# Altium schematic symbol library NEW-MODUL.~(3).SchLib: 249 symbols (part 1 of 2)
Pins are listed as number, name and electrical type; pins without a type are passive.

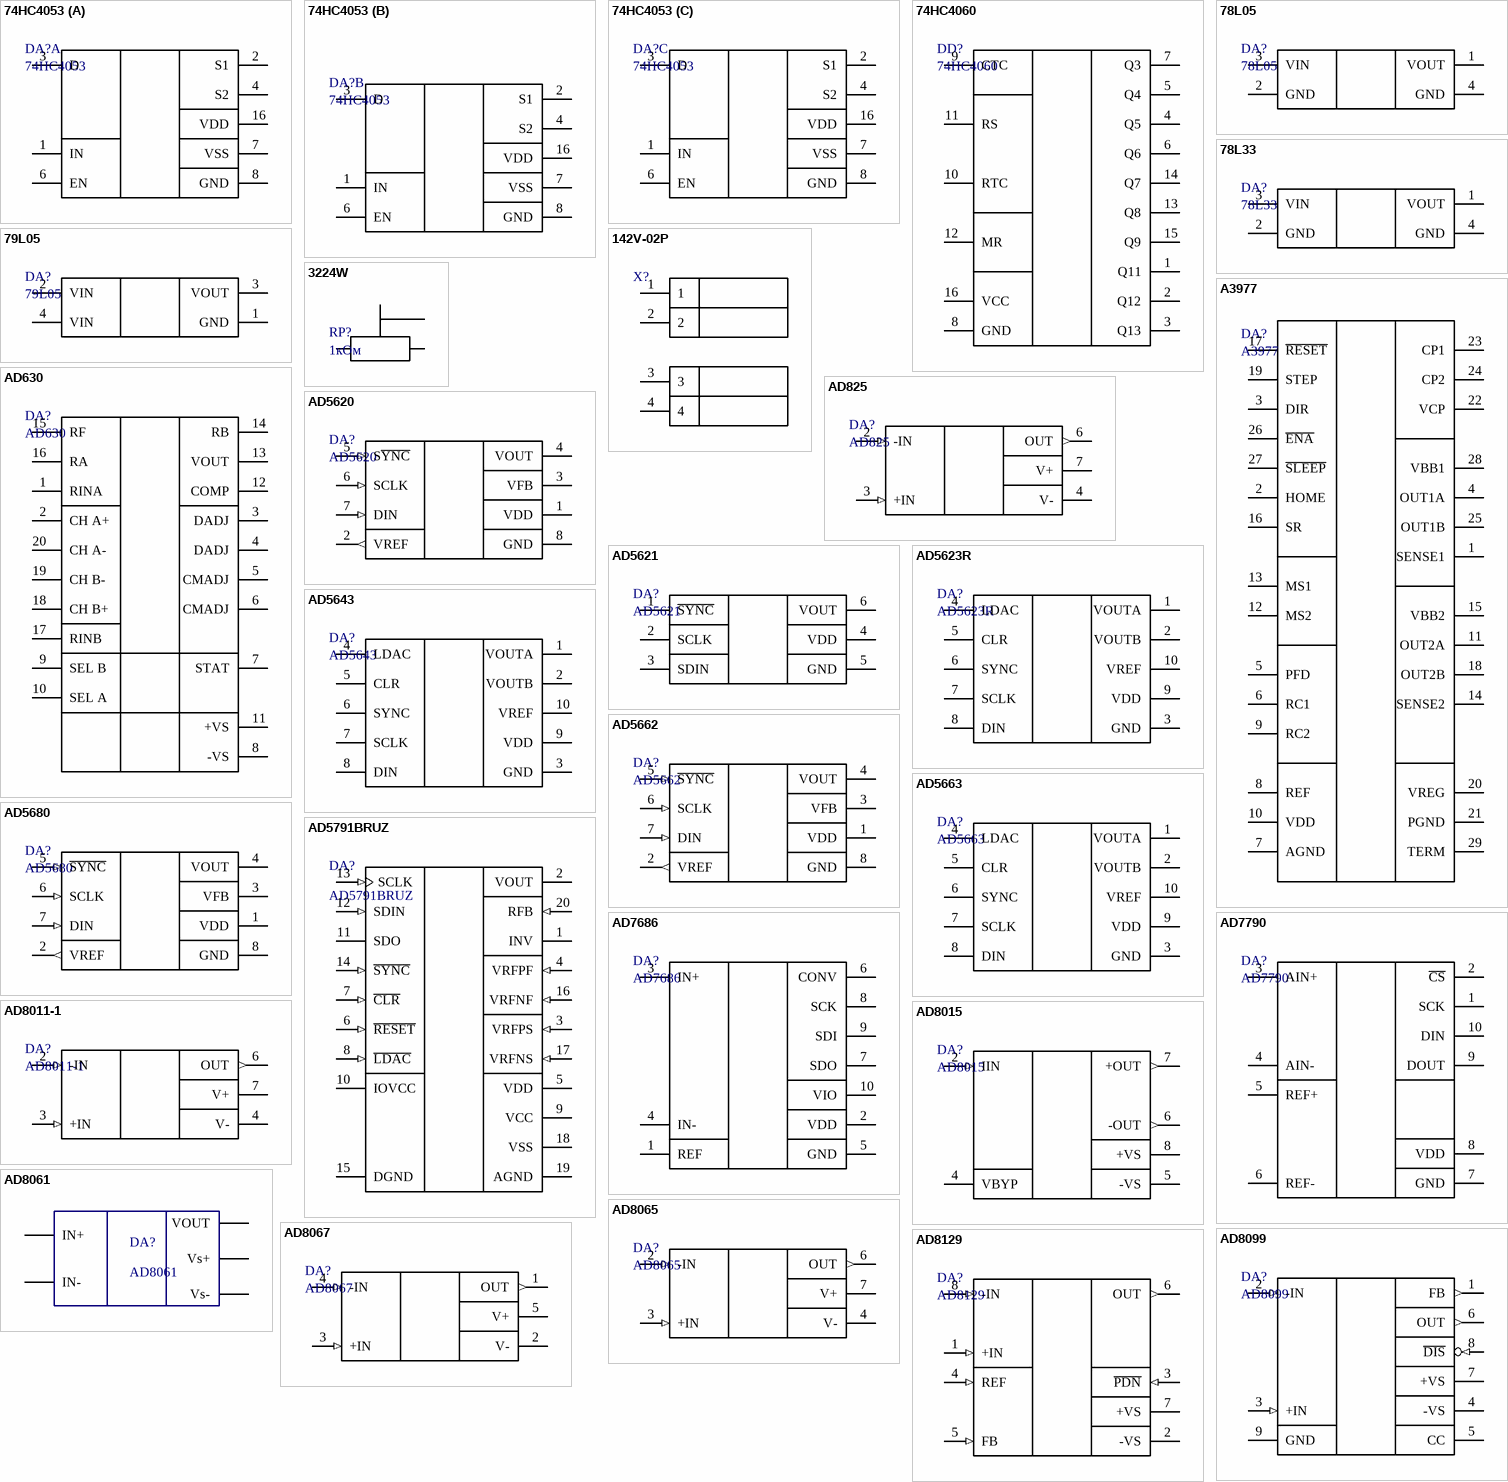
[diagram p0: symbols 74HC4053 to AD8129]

## 74HC4053
designator DA?
footprint R-16A_M (16-Pin Small Outline Integrated Circuit 1.27 mm Pitch, IPC Low Density)
part A pins: 1 IN, 2 S1, 3 D, 4 S2, 6 EN, 7 VSS, 8 GND, 16 VDD
part B pins: 1 IN, 2 S1, 3 D, 4 S2, 6 EN, 7 VSS, 8 GND, 16 VDD
part C pins: 1 IN, 2 S1, 3 D, 4 S2, 6 EN, 7 VSS, 8 GND, 16 VDD

## 74HC4060
designator DD?
14-stage binary ripple counter with oscillator
footprint R-16A_M (16-Pin Small Outline Integrated Circuit 1.27 mm Pitch, IPC Low Density)
pins: 1 Q11, 2 Q12, 3 Q13, 4 Q5, 5 Q4, 6 Q6, 7 Q3, 8 GND, 9 CTC, 10 RTC, 11 RS, 12 MR, 13 Q8, 14 Q7, 15 Q9, 16 VCC

## 78L05
designator DA?
footprint SOT89 (SOT-89; Body 4.6 x 4.25 mm, inc. leads (LxW max))
pins: 1 VOUT, 2 GND, 3 VIN, 4 GND

## 78L33
designator DA?
footprint SOT89 (SOT-89; Body 4.6 x 4.25 mm, inc. leads (LxW max))
pins: 1 VOUT, 2 GND, 3 VIN, 4 GND

## 79L05
designator DA?
footprint SOT89 (SOT-89; Body 4.6 x 4.25 mm, inc. leads (LxW max))
pins: 1 GND, 2 VIN, 3 VOUT, 4 VIN

## 142V-02P
designator X?  (value not drawn)
footprint 142V-02P
pins: 1, 2, 3, 4

## 3224W
designator RP?, comment 1кОм
подстроечный резистор
footprint 3224W
pins: 1, 2, 3

## A3977
designator DA?
footprint TSOP65P640-28AM - THERMAL-PAD (TSOP, 28-Leads, Body 9.7x4.4mm, Pitch 0.65mm, IPC Low Density)
pins: 1 SENSE1, 2 HOME, 3 DIR, 4 OUT1A, 5 PFD, 6 RC1, 7 AGND, 8 REF, 9 RC2, 10 VDD, 11 OUT2A, 12 MS2, 13 MS1, 14 SENSE2, 15 VBB2, 16 SR, 17 ~{RESET}, 18 OUT2B, 19 STEP, 20 VREG, 21 PGND, 22 VCP, 23 CP1, 24 CP2, 25 OUT1B, 26 ~{ENA}, 27 ~{SLEEP}, 28 VBB1, 29 TERM

## AD630
designator DA?
Balanced Modulator/Demodulator
footprint SOL-20_M (20-Pin Small Outline Integrated Circuit 1.27 mm Pitch, IPC Low Density)
pins: 1 RINA, 2 CH A+, 3 DADJ, 4 DADJ, 5 CMADJ, 6 CMADJ, 7 STAT, 8 -VS, 9 SEL B, 10 SEL A, 11 +VS, 12 COMP, 13 VOUT, 14 RB, 15 RF, 16 RA, 17 RINB, 18 CH B+, 19 CH B-, 20 CH A-

## AD825
designator DA?
FET OP
footprint SOIC127P600-8BM (SOIC, 8-Leads, Body 4.9x3.9mm, Pitch 1.27mm, IPC Low Density)
pins: 2 -IN (in), 3 +IN (in), 4 V- (power), 6 OUT (out), 7 V+ (power)

## AD5620
designator DA?
footprint UMAX8 (Shrink Small Outline; 8 Leads; Body Width 3 mm; Pitch 0.65 mm)
pins: 1 VDD (power), 2 VREF (out), 3 VFB, 4 VOUT, 5 S~{YNC} (in), 6 SCLK (in), 7 DIN (in), 8 GND

## AD5621
designator DA?
footprint ADI-KS-6_N (SOT23, 6-Leads, Body 2x1.25mm, Pitch 0.65mm, IPC Medium Density)
pins: 1 ~{SYNC}, 2 SCLK, 3 SDIN, 4 VDD, 5 GND, 6 VOUT

## AD5623R
designator DA?
footprint UMAX10 (Shrink Small Outline; 10 Leads; Body Width 3 mm; Pitch 0.5 mm)
pins: 1 VOUTA, 2 VOUTB, 3 GND, 4 LDAC, 5 CLR, 6 SYNC, 7 SCLK, 8 DIN, 9 VDD, 10 VREF

## AD5643
designator DA?
footprint UMAX10 (Shrink Small Outline; 10 Leads; Body Width 3 mm; Pitch 0.5 mm)
pins: 1 VOUTA, 2 VOUTB, 3 GND, 4 LDAC, 5 CLR, 6 SYNC, 7 SCLK, 8 DIN, 9 VDD, 10 VREF

## AD5662
designator DA?
footprint UMAX8 (Shrink Small Outline; 8 Leads; Body Width 3 mm; Pitch 0.65 mm)
pins: 1 VDD (power), 2 VREF (out), 3 VFB, 4 VOUT, 5 ~{SYNC} (in), 6 SCLK (in), 7 DIN (in), 8 GND

## AD5663
designator DA?
footprint UMAX10 (Shrink Small Outline; 10 Leads; Body Width 3 mm; Pitch 0.5 mm)
pins: 1 VOUTA, 2 VOUTB, 3 GND, 4 LDAC, 5 CLR, 6 SYNC, 7 SCLK, 8 DIN, 9 VDD, 10 VREF

## AD5680
designator DA?
5 V 18-Bit nanoDAC
footprint RJ-8_N (SOP, 8-Leads, Body 2.9x1.6mm, Pitch 0.65mm, IPC Medium Density)
pins: 1 VDD (power), 2 VREF (out), 3 VFB, 4 VOUT, 5 ~{SYNC} (in), 6 SCLK (in), 7 DIN (in), 8 GND

## AD5791BRUZ
designator DA?
Single 20-Bit Voltage Output Digital-to-Analog Converter, 1 ppm, -40 to +125 degC, RU-20, Pb-Free, Tube; ADI Part Number: AD5791; Manufacturer: Analog Devices; # DAC Outputs: 1; Max V+: 16.5V; Op Pwr Diss: 126.3mW; Resolution (Bits): 20; Settling Time: 1µs; Single Supply: No
footprint TSOP65P640-20BM (TSOP, 20-Leads, Body 6.5x4.4mm, Pitch 0.65mm, IPC Low Density)
pins: 1 INV "Connection to Inverting Input of External Amplifier. See the AD5791 Features section for further details.", 2 VOUT (hiz) "Analog Output Voltage.", 3 VRFPS (in) "Positive Reference Sense Voltage Input. A voltage range of 5 V to VDD - 2.5 V can be connected. A unity gain amplifier must be connected at this pin in conjunction with the VREFPF pin. See the AD5791 Features section for (See Datasheet)", 4 VRFPF (in) "Positive Reference Force Voltage Input. A voltage range of 5 V to VDD - 2.5 V can be connected. A unity gain amplifier must be connected at this pin in conjunction with the VREFPS pin. See the AD5791 Features section for (See Datasheet)", 5 VDD (power) "Positive Analog Supply Connection. A voltage range of 7.5 V to 16.5 V can be connected, VDD should be decoupled to AGND.", 6 ~{RESET} (in) "Active Low Reset Logic Input Pin. Asserting this pin returns the AD5791 to its power-on status.", 7 ~{CLR} (in) "Active Low Clear Logic Input Pin. Asserting this pin sets the DAC register to a user defined value (see Table 13) and updates the DAC output. The output value depends on the DAC register coding that is being used, either (See Datasheet)", 8 ~{LDAC} (in) "Active Low Load DAC Logic Input Pin. This is used to update the DAC register and consequently, the analog output. When tied permanently low, the output is updated on the rising edge of S\Y\N\C\. If L\D\A\C\ is held high (See Datasheet)", 9 VCC (power) "Digital Supply Connection. A voltage range of 2.7 V to 5.5 V can be connected. VCC should be decoupled to DGND.", 10 IOVCC (power) "Digital Interface Supply Pin. Digital threshold levels are referenced to the voltage applied to this pin. A voltage in the range of 1.71 V to 5.5 V can be connected. IOVCC should not be allowed to exceed VCC.", 11 SDO (hiz) "Serial Data Output Pin. Data is clocked out on the rising edge of the serial clock input.", 12 SDIN (in) "Serial Data Input Pin. This device has a 24-bit shift register. Data is clocked into the register on the falling edge of the serial clock input.", 13 SCLK (in) "Serial Clock Input. Data is clocked into the input shift register on the falling edge of the serial clock input. Data can be transferred at clock rates of up to 35 MHz.", 14 ~{SYNC} (in) "Active Low Digital Interface Synchronization Input Pin. This is the frame synchronization signal for the input data. When S\Y\N\C\ is low, it enables the input shift register, and data is then transferred in on the falling (See Datasheet)", 15 DGND (power) "Ground Reference Pin for Digital Circuitry.", 16 VRFNF (in) "Negative Reference Force Voltage Input. A voltage range of VSS + 2.5 V to 0 V can be connected. A unity gain amplifier must be connected at this pin, in conjunction with the VREFNS pin. See the AD5791 Features section for (See Datasheet)", 17 VRFNS (in) "Negative Reference Sense Voltage Input. A voltage range of VSS + 2.5 V to 0 V can be connected. A unity gain amplifier must be connected at this pin, in conjunction with the VREFNF pin. See the AD5791 Features section for (See Datasheet)", 18 VSS (power) "Negative Analog Supply Connection. A voltage range of -16.5 V to -2.5 V can be connected. VSS should be decoupled to AGND.", 19 AGND (power) "Ground Reference Pin for Analog Circuitry.", 20 RFB (in) "Feedback Connection for External Amplifier. See the AD5791 Features section for further details."

## AD7686
designator DA?
footprint UMAX10 (Shrink Small Outline; 10 Leads; Body Width 3 mm; Pitch 0.5 mm)
pins: 1 REF, 2 VDD, 3 IN+, 4 IN-, 5 GND, 6 CONV, 7 SDO, 8 SCK, 9 SDI, 10 VIO

## AD7790
designator DA?
footprint UMAX10 (Shrink Small Outline; 10 Leads; Body Width 3 mm; Pitch 0.5 mm)
pins: 1 SCK, 2 ~{CS}, 3 AIN+, 4 AIN-, 5 REF+, 6 REF-, 7 GND, 8 VDD, 9 DOUT, 10 DIN

## AD8011-1
designator DA?
Current Feedback Amplifier
footprint SOIC127P600-8BM (SOIC, 8-Leads, Body 4.9x3.9mm, Pitch 1.27mm, IPC Low Density)
pins: 2 -IN (in), 3 +IN (in), 4 V- (power), 6 OUT (out), 7 V+ (power)

## AD8015
designator DA?
Трансимпедансный усилитель
footprint SOIC127P600-8BM (SOIC, 8-Leads, Body 4.9x3.9mm, Pitch 1.27mm, IPC Low Density)
pins: 2 IIN (in), 4 VBYP, 5 -VS (power), 6 -OUT (out), 7 +OUT (out), 8 +VS (power)

## AD8061
designator DA?
OpAmp, Rail-toRail
footprint SOT23-5AM (SOT23, 5-Leads, Body 2.9x1.7mm, Pitch 0.95mm, Lead Span 2.8mm, IPC Low Density)
pins: 1 VOUT, 2 Vs-, 3 IN+, 4 IN-, 5 Vs+

## AD8065
designator DA?
FET OP
footprint SOIC127P600-8BM (SOIC, 8-Leads, Body 4.9x3.9mm, Pitch 1.27mm, IPC Low Density)
pins: 2 -IN (in), 3 +IN (in), 4 V- (power), 6 OUT (out), 7 V+ (power)

## AD8067
designator DA?
FET OP
footprint SOT23-5AM (SOT23, 5-Leads, Body 2.9x1.7mm, Pitch 0.95mm, Lead Span 2.8mm, IPC Low Density)
pins: 1 OUT (out), 2 V- (power), 3 +IN (in), 4 -IN (in), 5 V+ (power)

## AD8099
designator DA?
footprint SOIC_N_EP (8-Pin Small Outline Integrated Circuit 1.27 mm Pitch, IPC High Density)
pins: 1 FB (out), 2 -IN (in), 3 +IN (in), 4 -VS (power), 5 CC (power), 6 OUT (out), 7 +VS (power), 8 ~{DIS} (in), 9 GND

## AD8129
designator DA?
differential-to-single-ended amplifier
footprint SOIC127P600-8BM (SOIC, 8-Leads, Body 4.9x3.9mm, Pitch 1.27mm, IPC Low Density)
pins: 1 +IN (in), 2 -VS (power), 3 ~{PDN} (in), 4 REF (in), 5 FB (in), 6 OUT (out), 7 +VS (power), 8 -IN (in)

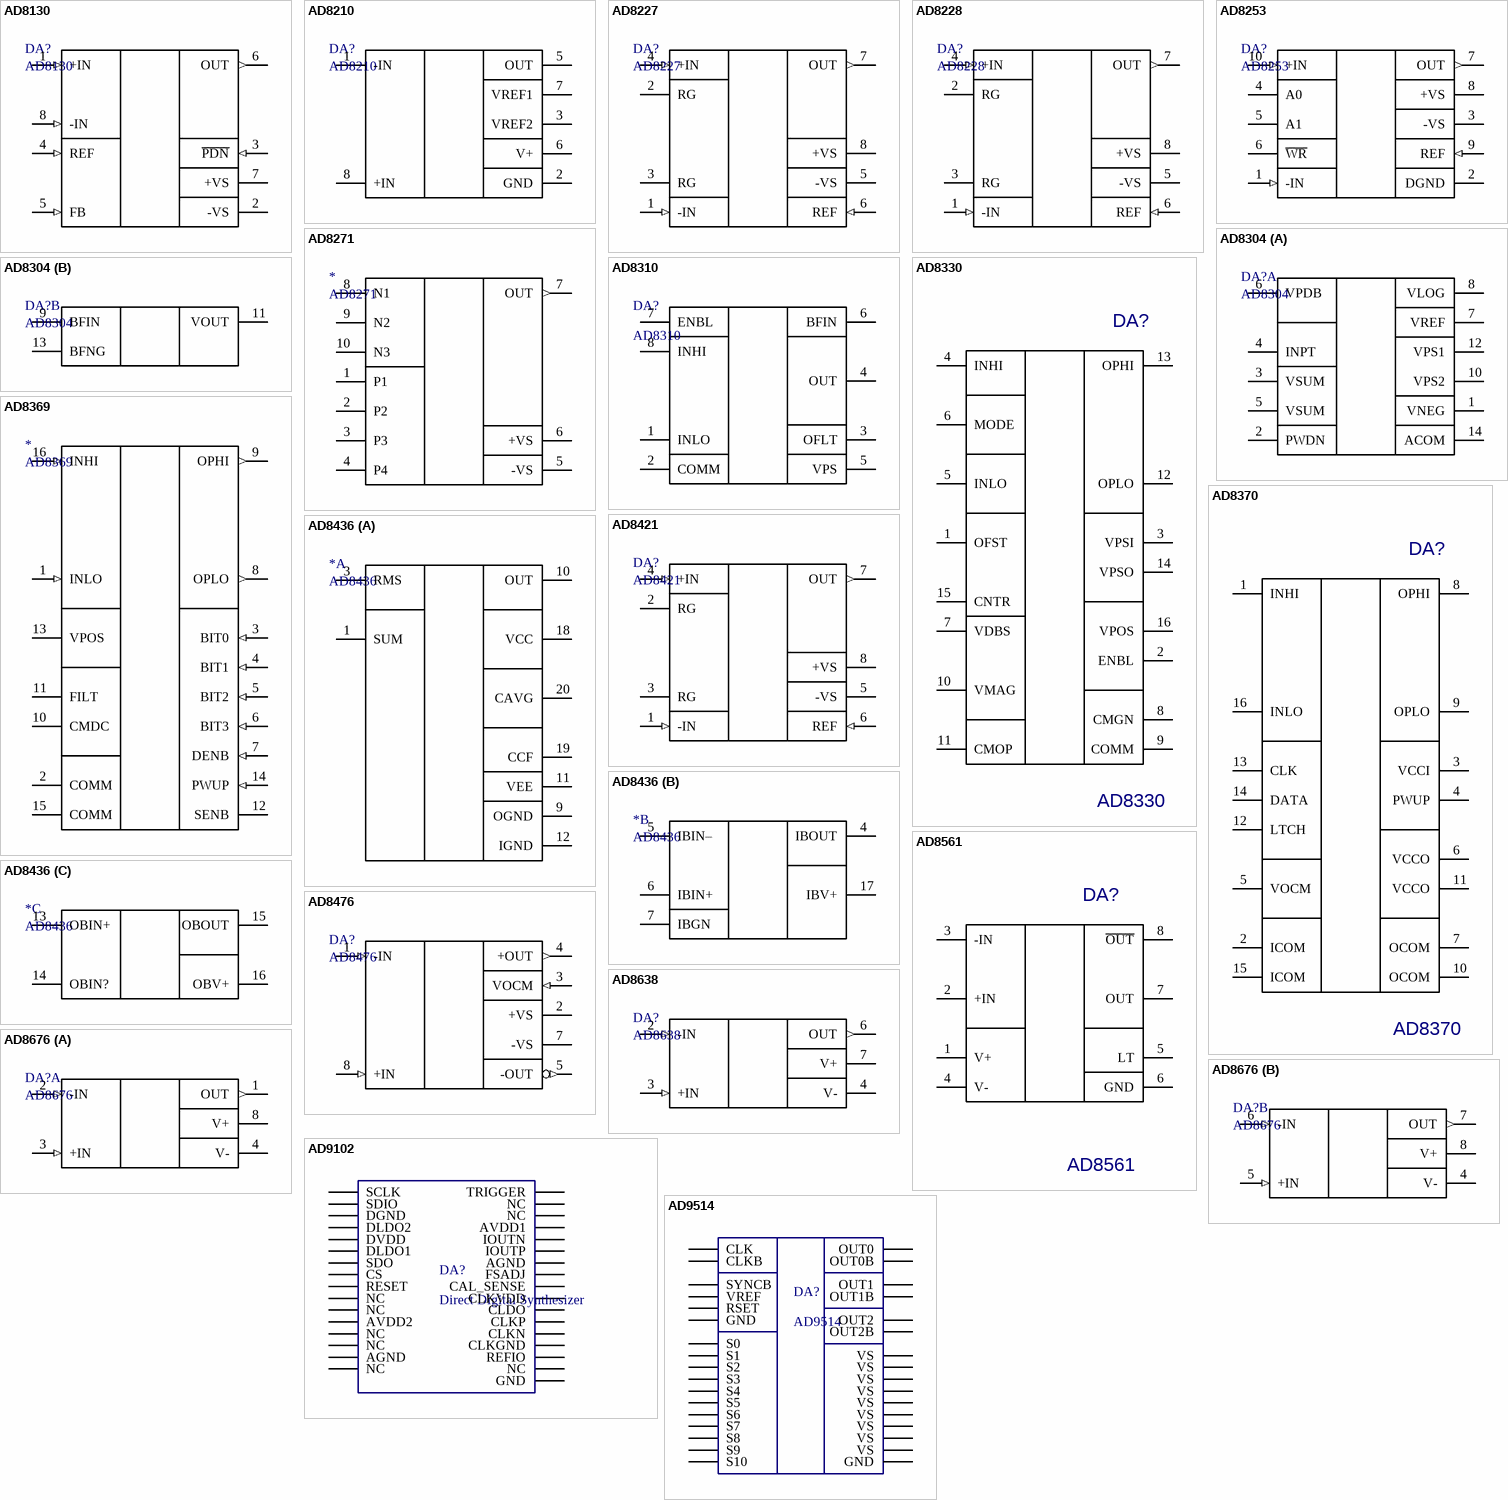
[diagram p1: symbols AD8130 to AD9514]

## AD8130
designator DA?
differential-to-single-ended amplifier
footprint SOIC127P600-8BM (SOIC, 8-Leads, Body 4.9x3.9mm, Pitch 1.27mm, IPC Low Density)
pins: 1 +IN (in), 2 -VS (power), 3 ~{PDN} (in), 4 REF (in), 5 FB (in), 6 OUT (out), 7 +VS (power), 8 -IN (in)

## AD8210
designator DA?
High Voltage, Bidirectional  Current Shunt Monitor
footprint SOIC127P600-8BM (SOIC, 8-Leads, Body 4.9x3.9mm, Pitch 1.27mm, IPC Low Density)
pins: 1 -IN, 2 GND, 3 VREF2, 5 OUT, 6 V+, 7 VREF1, 8 +IN

## AD8227
designator DA?
instrumentation amplifier
footprint SO-8_L (8-Pin Small Outline Integrated Circuit 1.27 mm Pitch, IPC High Density)
pins: 1 -IN (in), 2 RG, 3 RG, 4 +IN (in), 5 -VS (power), 6 REF (in), 7 OUT (out), 8 +VS (power)

## AD8228
designator DA?
instrumentation amplifier
footprint SO-8_L (8-Pin Small Outline Integrated Circuit 1.27 mm Pitch, IPC High Density)
pins: 1 -IN (in), 2 RG, 3 RG, 4 +IN (in), 5 -VS (power), 6 REF (in), 7 OUT (out), 8 +VS (power)

## AD8253
designator DA?
instrumentation amplifier
footprint UMAX10 (Shrink Small Outline; 10 Leads; Body Width 3 mm; Pitch 0.5 mm)
pins: 1 -IN (in), 2 DGND, 3 -VS (power), 4 A0, 5 A1, 6 ~{WR}, 7 OUT (out), 8 +VS (power), 9 REF (in), 10 +IN (in)

## AD8271
designator *
footprint UMAX10 (Shrink Small Outline; 10 Leads; Body Width 3 mm; Pitch 0.5 mm)
pins: 1 P1, 2 P2, 3 P3, 4 P4, 5 -VS (power), 6 +VS (power), 7 OUT (out), 8 N1, 9 N2, 10 N3

## AD8304
designator DA?
160 dB Range (100 pA –10 mA)  Logarithmic Converter
footprint ADI-RU-14_N (SOP, 14-Leads, Body 5x4.4mm, Pitch 0.65mm, IPC Medium Density)
part A pins: 1 VNEG, 2 PWDN, 3 VSUM, 4 INPT, 5 VSUM, 6 VPDB, 7 VREF, 8 VLOG, 10 VPS2, 12 VPS1, 14 ACOM
part B pins: 9 BFIN, 11 VOUT, 13 BFNG

## AD8310
designator DA?
footprint UMAX8 (Shrink Small Outline; 8 Leads; Body Width 3 mm; Pitch 0.65 mm)
pins: 1 INLO, 2 COMM, 3 OFLT, 4 OUT, 5 VPS, 6 BFIN, 7 ENBL, 8 INHI

## AD8330
designator DA?
footprint QSOP16
pins: 1 OFST, 2 ENBL, 3 VPSI, 4 INHI, 5 INLO, 6 MODE, 7 VDBS, 8 CMGN, 9 COMM, 10 VMAG, 11 CMOP, 12 OPLO, 13 OPHI, 14 VPSO, 15 CNTR, 16 VPOS

## AD8369
designator *
footprint QSOP16
pins: 1 INLO (in), 2 COMM, 3 BIT0 (in), 4 BIT1 (in), 5 BIT2 (in), 6 BIT3 (in), 7 DENB (in), 8 OPLO (out), 9 OPHI (out), 10 CMDC, 11 FILT, 12 SENB, 13 VPOS, 14 PWUP (in), 15 COMM, 16 INHI (in)

## AD8370
designator DA?
footprint QSOP16
pins: 1 INHI, 2 ICOM, 3 VCCI, 4 PWUP, 5 VOCM, 6 VCCO, 7 OCOM, 8 OPHI, 9 OPLO, 10 OCOM, 11 VCCO, 12 LTCH, 13 CLK, 14 DATA, 15 ICOM, 16 INLO

## AD8421
designator DA?
instrumentation amplifier
footprint SO-8_L (8-Pin Small Outline Integrated Circuit 1.27 mm Pitch, IPC High Density)
pins: 1 -IN (in), 2 RG, 3 RG, 4 +IN (in), 5 -VS (power), 6 REF (in), 7 OUT (out), 8 +VS (power)

## AD8436
designator *
footprint QSOP20
part A pins: 1 SUM, 3 RMS, 9 OGND, 10 OUT, 11 VEE, 12 IGND, 18 VCC, 19 CCF, 20 CAVG
part B pins: 4 IBOUT, 5 IBIN–, 6 IBIN+, 7 IBGN, 17 IBV+
part C pins: 13 OBIN+, 14 OBIN?, 15 OBOUT, 16 OBV+

## AD8476
designator DA?
Low Power, Unity Gain, Fully  Differential Amplifier and ADC Driver
footprint UMAX8 (Shrink Small Outline; 8 Leads; Body Width 3 mm; Pitch 0.65 mm)
pins: 1 -IN (in), 2 +VS (power), 3 VOCM (in), 4 +OUT (out), 5 -OUT (out), 7 -VS (power), 8 +IN (in)

## AD8561
designator DA?
footprint SOIC127P600-8BM (SOIC, 8-Leads, Body 4.9x3.9mm, Pitch 1.27mm, IPC Low Density)
pins: 1 V+, 2 +IN, 3 -IN, 4 V-, 5 LT, 6 GND, 7 OUT, 8 ~{OUT}

## AD8638
designator DA?
OP
footprint SOIC127P600-8BM (SOIC, 8-Leads, Body 4.9x3.9mm, Pitch 1.27mm, IPC Low Density)
pins: 2 -IN (in), 3 +IN (in), 4 V- (power), 6 OUT (out), 7 V+ (power)

## AD8676
designator DA?
Ultra Precision, 36 V, 2.8 nV/√Hz Dual RRO Op Amp
footprint SOIC127P600-8BM (SOIC, 8-Leads, Body 4.9x3.9mm, Pitch 1.27mm, IPC Low Density)
part A pins: 1 OUT (out), 2 -IN (in), 3 +IN (in), 4 V- (power), 8 V+ (power)
part B pins: 4 V- (power), 5 +IN (in), 6 -IN (in), 7 OUT (out), 8 V+ (power)

## AD9102
designator DA?, comment Direct Digital Synthesizer
footprint CP-32-2_M (QFN, 32-Leads, Body 5x5mm, Pitch 0.5mm, Thermal Pad 3.1x3.1mm, IPC Low Density)
pins: 1 SCLK, 2 SDIO, 3 DGND, 4 DLDO2, 5 DVDD, 6 DLDO1, 7 SDO, 8 CS, 9 RESET, 10 NC, 11 NC, 12 AVDD2, 13 NC, 14 NC, 15 AGND, 16 NC, 17 NC, 18 REFIO, 19 CLKGND, 20 CLKN, 21 CLKP, 22 CLDO, 23 CLKVDD, 24 CAL_SENSE, 25 FSADJ, 26 AGND, 27 IOUTP, 28 IOUTN, 29 AVDD1, 30 NC, 31 NC, 32 TRIGGER, 33 GND

## AD9514
designator DA?
footprint CP-32-2_M (QFN, 32-Leads, Body 5x5mm, Pitch 0.5mm, Thermal Pad 3.1x3.1mm, IPC Low Density)
pins: 1 VS, 2 CLK, 3 CLKB, 4 VS, 5 SYNCB, 6 VREF, 7 S10, 8 S9, 9 S8, 10 S7, 11 S6, 12 S5, 13 S4, 14 S3, 15 S2, 16 S1, 17 VS, 18 OUT2B, 19 OUT2, 20 VS, 21 VS, 22 OUT1B, 23 OUT1, 24 VS, 25 S0, 26 VS, 27 OUT0B, 28 OUT0, 29 VS, 30 VS, 31 GND, 32 RSET, 33 GND

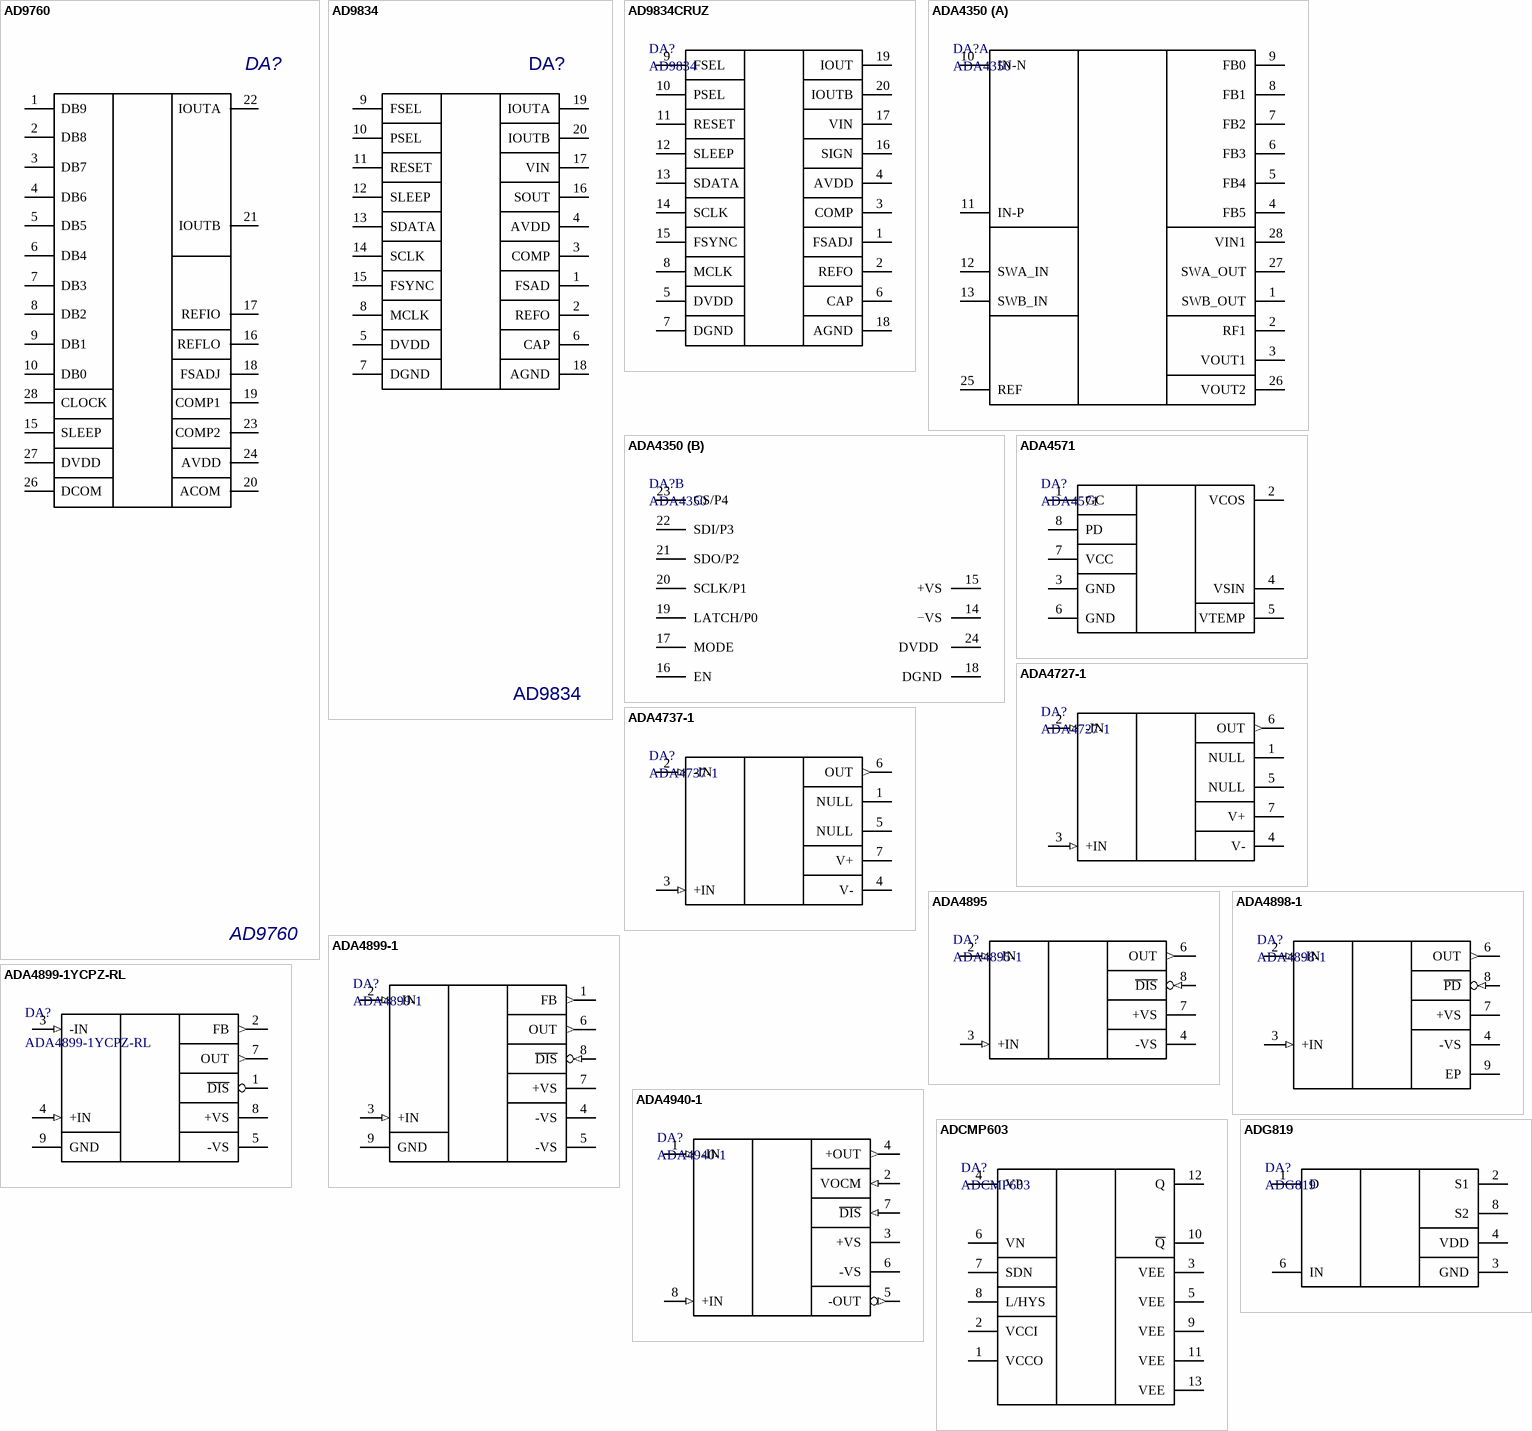
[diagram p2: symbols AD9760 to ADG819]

## AD9760
designator DA?
AD9760 TXDAC
footprint TSOP65P640-28AM (TSOP, 28-Leads, Body 9.7x4.4mm, Pitch 0.65mm, IPC Low Density)
pins: 1 DB9, 2 DB8, 3 DB7, 4 DB6, 5 DB5, 6 DB4, 7 DB3, 8 DB2, 9 DB1, 10 DB0, 11 hidden, 12 hidden, 13 hidden, 14 hidden, 15 SLEEP, 16 REFLO, 17 REFIO, 18 FSADJ, 19 COMP1, 20 ACOM, 21 IOUTB, 22 IOUTA, 23 COMP2, 24 AVDD, 25 hidden, 26 DCOM, 27 DVDD, 28 CLOCK

## AD9834
designator DA?
AD9834 синтезатор частоты
footprint TSOP65P640-20BM (TSOP, 20-Leads, Body 6.5x4.4mm, Pitch 0.65mm, IPC Low Density)
pins: 1 FSAD, 2 REFO, 3 COMP, 4 AVDD, 5 DVDD, 6 CAP, 7 DGND, 8 MCLK, 9 FSEL, 10 PSEL, 11 RESET, 12 SLEEP, 13 SDATA, 14 SCLK, 15 FSYNC, 16 SOUT, 17 VIN, 18 AGND, 19 IOUTA, 20 IOUTB

## AD9834CRUZ
designator DA?, comment AD9834
75 MHz Complete DDS
footprint TSOP65P640-20BM (TSOP, 20-Leads, Body 6.5x4.4mm, Pitch 0.65mm, IPC Low Density)
pins: 1 FSADJ, 2 REFO, 3 COMP, 4 AVDD, 5 DVDD (power), 6 CAP, 7 DGND (power), 8 MCLK, 9 FSEL, 10 PSEL, 11 RESET, 12 SLEEP, 13 SDATA, 14 SCLK, 15 FSYNC, 16 SIGN, 17 VIN, 18 AGND (power), 19 IOUT, 20 IOUTB

## ADA4350
designator DA?
FET Input Analog Front End  with ADC Driver
footprint RU-28_M (TSOP, 28-Leads, Body 9.7x4.4mm, Pitch 0.65mm, IPC Low Density)
part A pins: 1 SWB_OUT, 2 RF1, 3 VOUT1, 4 FB5, 5 FB4, 6 FB3, 7 FB2, 8 FB1, 9 FB0, 10 IN-N , 11 IN-P , 12 SWA_IN , 13 SWB_IN , 25 REF , 26 VOUT2, 27 SWA_OUT, 28 VIN1
part B pins: 14 −VS, 15 +VS, 16 EN , 17 MODE, 18 DGND, 19 LATCH/P0, 20 SCLK/P1 , 21 SDO/P2 , 22 SDI/P3, 23 CS/P4 , 24 DVDD 

## ADA4571
designator DA?
footprint SOIC127P600-8BM (SOIC, 8-Leads, Body 4.9x3.9mm, Pitch 1.27mm, IPC Low Density)
pins: 1 GC, 2 VCOS, 3 GND, 4 VSIN, 5 VTEMP, 6 GND, 7 VCC, 8 PD

## ADA4727-1
designator DA?
FET OP
footprint SOIC127P600-8BM (SOIC, 8-Leads, Body 4.9x3.9mm, Pitch 1.27mm, IPC Low Density)
pins: 1 NULL, 2 -IN (in), 3 +IN (in), 4 V- (power), 5 NULL, 6 OUT (out), 7 V+ (power)

## ADA4737-1
designator DA?
FET OP
footprint SOIC127P600-8BM (SOIC, 8-Leads, Body 4.9x3.9mm, Pitch 1.27mm, IPC Low Density)
pins: 1 NULL, 2 -IN (in), 3 +IN (in), 4 V- (power), 5 NULL, 6 OUT (out), 7 V+ (power)

## ADA4895
designator DA?, comment ADA4895-1
OUTPUT AMPLIFIER
footprint SOIC127P600-8BM (SOIC, 8-Leads, Body 4.9x3.9mm, Pitch 1.27mm, IPC Low Density)
pins: 2 -IN (in), 3 +IN (in), 4 -VS (power), 6 OUT (out), 7 +VS (power), 8 ~{DIS} (in)

## ADA4898-1
designator DA?
LowNoise OPA
footprint SOIC_N_EP (8-Pin Small Outline Integrated Circuit 1.27 mm Pitch, IPC High Density)
pins: 2 -IN (in), 3 +IN (in), 4 -VS (power), 6 OUT (out), 7 +VS (power), 8 ~{PD} (in), 9 EP

## ADA4899-1
designator DA?
footprint SOIC_N_EP (8-Pin Small Outline Integrated Circuit 1.27 mm Pitch, IPC High Density)
pins: 1 FB (out), 2 -IN (in), 3 +IN (in), 4 -VS (power), 5 -VS (power), 6 OUT (out), 7 +VS (power), 8 ~{DIS} (in), 9 GND

## ADA4899-1YCPZ-RL
designator DA?
Single Channel Ultra Low Noise Operational Amplifier, 600 MHz BW, 310 V/us SR, Industrial, 8-pin QFN (CP-8-2), Reel; Manufacturer: Analog Devices; Amplifiers Per Package: 1; Input Bias Current: 100nA; Input Offset Voltage: 35uV; Iq/Amp: 16.2mA; Small Signal Bandwidth: 600MHz; V Span Max: 12V; V Span Min: 4.5V
footprint ADI-CP-8-2_M (QFN, 8-Leads, Body 3x3mm, Pitch 0.5mm, Thermal Pad 1.45X1.74mm, IPC Low Density)
pins: 1 ~{DIS} (hiz), 2 FB (out), 3 -IN (in), 4 +IN (in), 5 -VS (power), 7 OUT (out), 8 +VS (power), 9 GND

## ADA4940-1
designator DA?
Differential ADC driver
footprint SOIC127P600-8BM (SOIC, 8-Leads, Body 4.9x3.9mm, Pitch 1.27mm, IPC Low Density)
pins: 1 -IN (in), 2 VOCM (in), 3 +VS (power), 4 +OUT (out), 5 -OUT (out), 6 -VS (power), 7 ~{DIS} (in), 8 +IN (in)

## ADCMP603
designator DA?
footprint QFN50P300X275X100-12M (QFN, 12-Leads, Body 3,0x2,8mm (max), Pitch 0,50mm, IPC Low Density)
pins: 1 VCCO, 2 VCCI, 3 VEE, 4 VP, 5 VEE, 6 VN, 7 SDN, 8 L/HYS, 9 VEE, 10 ~{Q}, 11 VEE, 12 Q, 13 VEE

## ADG819
designator DA?
footprint UMAX8 (Shrink Small Outline; 8 Leads; Body Width 3 mm; Pitch 0.65 mm)
pins: 1 D, 2 S1, 3 GND, 4 VDD, 6 IN, 8 S2

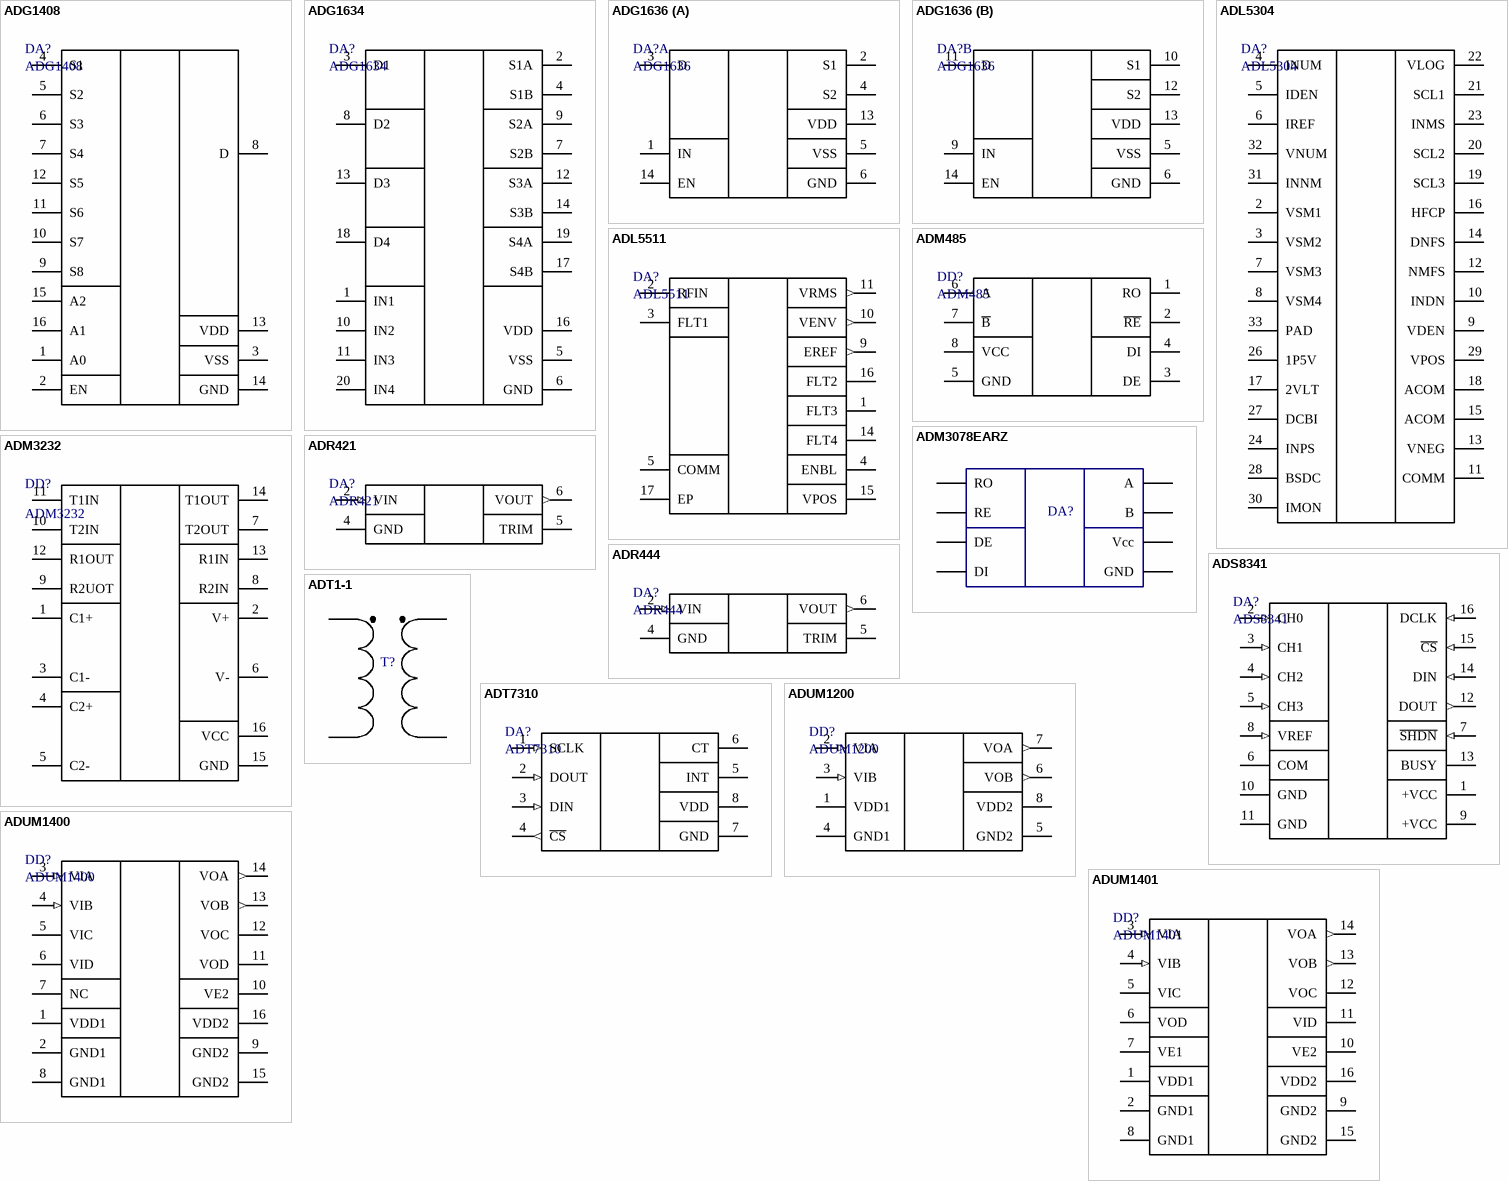
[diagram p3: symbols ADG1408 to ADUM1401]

## ADG1408
designator DA?
footprint ADI-RU-16_M (SOP, 16-Leads, Body 5x4.4mm, Pitch 0.65mm, IPC Low Density)
pins: 1 A0 , 2 EN , 3 VSS, 4 S1, 5 S2, 6 S3, 7 S4, 8 D, 9 S8, 10 S7, 11 S6, 12 S5, 13 VDD, 14 GND, 15 A2, 16 A1

## ADG1634
designator DA?
footprint TSOP65P640-20BM (TSOP, 20-Leads, Body 6.5x4.4mm, Pitch 0.65mm, IPC Low Density)
pins: 1 IN1, 2 S1A, 3 D1, 4 S1B, 5 VSS, 6 GND, 7 S2B, 8 D2, 9 S2A, 10 IN2, 11 IN3, 12 S3A, 13 D3, 14 S3B, 16 VDD, 17 S4B, 18 D4, 19 S4A, 20 IN4

## ADG1636
designator DA?
footprint ADI-RU-16_M (SOP, 16-Leads, Body 5x4.4mm, Pitch 0.65mm, IPC Low Density)
part A pins: 1 IN, 2 S1, 3 D, 4 S2, 5 VSS, 6 GND, 13 VDD, 14 EN
part B pins: 5 VSS, 6 GND, 9 IN, 10 S1, 11 D, 12 S2, 13 VDD, 14 EN

## ADL5304
designator DA?
footprint CP-32-2_M (QFN, 32-Leads, Body 5x5mm, Pitch 0.5mm, Thermal Pad 3.1x3.1mm, IPC Low Density)
pins: 2 VSM1, 3 VSM2, 4 INUM, 5 IDEN, 6 IREF, 7 VSM3, 8 VSM4, 9 VDEN, 10 INDN, 11 COMM, 12 NMFS, 13 VNEG, 14 DNFS, 15 ACOM, 16 HFCP, 17 2VLT, 18 ACOM, 19 SCL3, 20 SCL2, 21 SCL1, 22 VLOG, 23 INMS, 24 INPS, 26 1P5V, 27 DCBI, 28 BSDC, 29 VPOS, 30 IMON, 31 INNM, 32 VNUM, 33 PAD

## ADL5511
designator DA?
DC to 6 GHz  Envelope and TruPwr RMS Detector
footprint CP-16-22_M (QFN, 16-Leads, Body 3x3mm, Pitch 0.5mm, Thermal Pad 1.75x1.75mm, IPC Low Density)
pins: 1 FLT3, 2 RFIN, 3 FLT1, 4 ENBL, 5 COMM (power), 9 EREF (out), 10 VENV (out), 11 VRMS (out), 14 FLT4, 15 VPOS (power), 16 FLT2, 17 EP (power)

## ADM485
designator DD?
footprint SOIC127P600-8BM (SOIC, 8-Leads, Body 4.9x3.9mm, Pitch 1.27mm, IPC Low Density)
pins: 1 RO, 2 ~{RE}, 3 DE, 4 DI, 5 GND, 6 A, 7 ~{B}, 8 VCC

## ADM3078EARZ
designator DA?  (value not drawn)
footprint ADM3078EARZ
pins: 1 RO, 2 RE, 3 DE, 4 DI, 5 GND, 6 A, 7 B, 8 Vcc

## ADM3232
designator DD?
footprint R-16A_M (16-Pin Small Outline Integrated Circuit 1.27 mm Pitch, IPC Low Density)
pins: 1 C1+, 2 V+, 3 C1-, 4 C2+, 5 C2-, 6 V-, 7 T2OUT, 8 R2IN, 9 R2UOT, 10 T2IN, 11 T1IN, 12 R1OUT, 13 R1IN, 14 T1OUT, 15 GND, 16 VCC

## ADR421
designator DA?
Источник опорного напряжения
footprint SOIC127P600-8BM (SOIC, 8-Leads, Body 4.9x3.9mm, Pitch 1.27mm, IPC Low Density)
pins: 2 VIN (in), 4 GND (power), 5 TRIM, 6 VOUT (out)

## ADR444
designator DA?
Источник опорного напряжения 4,096В
footprint SOIC127P600-8BM (SOIC, 8-Leads, Body 4.9x3.9mm, Pitch 1.27mm, IPC Low Density)
pins: 2 VIN (in), 4 GND (power), 5 TRIM, 6 VOUT (out)

## ADS8341
designator DA?
footprint DBQ016 (SSOP; 16 Leads; Body Width 3.9 mm; Pitch 0.635 mm)
pins: 1 +VCC (power), 2 CH0 (in), 3 CH1 (in), 4 CH2 (in), 5 CH3 (in), 6 COM (power), 7 ~{SHDN} (in), 8 VREF (in), 9 +VCC (power), 10 GND (power), 11 GND (power), 12 DOUT (out), 13 BUSY, 14 DIN (in), 15 ~{CS} (in), 16 DCLK (in)

## ADT1-1
designator T?  (value not drawn)
Balun
footprint Adt1-1
pins: 1 P, 3 Pdot, 4 Sdot, 6 S

## ADT7310
designator DA?
±0.5°C Accurate, 16-Bit  Digital SPI Temperature Sensor
footprint SOIC127P600-8BM (SOIC, 8-Leads, Body 4.9x3.9mm, Pitch 1.27mm, IPC Low Density)
pins: 1 SCLK (in), 2 DOUT (in), 3 DIN (in), 4 ~{CS} (out), 5 INT, 6 CT, 7 GND, 8 VDD (power)

## ADUM1200
designator DD?
dual-channel digital isolator
footprint SOIC127P600-8BM (SOIC, 8-Leads, Body 4.9x3.9mm, Pitch 1.27mm, IPC Low Density)
pins: 1 VDD1 (power), 2 VIA (in), 3 VIB (in), 4 GND1, 5 GND2 (power), 6 VOB (out), 7 VOA (out), 8 VDD2 (power)

## ADUM1400
designator DD?
4-channel digital isolator
footprint RW-16_M (16-Pin Wide Body Small Outline Integrated Circuit 1.27 mm Pitch, IPC Low Density)
pins: 1 VDD1 (power), 2 GND1, 3 VIA (in), 4 VIB (in), 5 VIC, 6 VID, 7 NC, 8 GND1, 9 GND2 (power), 10 VE2, 11 VOD, 12 VOC, 13 VOB (out), 14 VOA (out), 15 GND2, 16 VDD2 (power)

## ADUM1401
designator DD?
dual-channel digital isolator
footprint RW-16_M (16-Pin Wide Body Small Outline Integrated Circuit 1.27 mm Pitch, IPC Low Density)
pins: 1 VDD1 (power), 2 GND1, 3 VIA (in), 4 VIB (in), 5 VIC, 6 VOD, 7 VE1, 8 GND1, 9 GND2 (power), 10 VE2, 11 VID, 12 VOC, 13 VOB (out), 14 VOA (out), 15 GND2, 16 VDD2 (power)

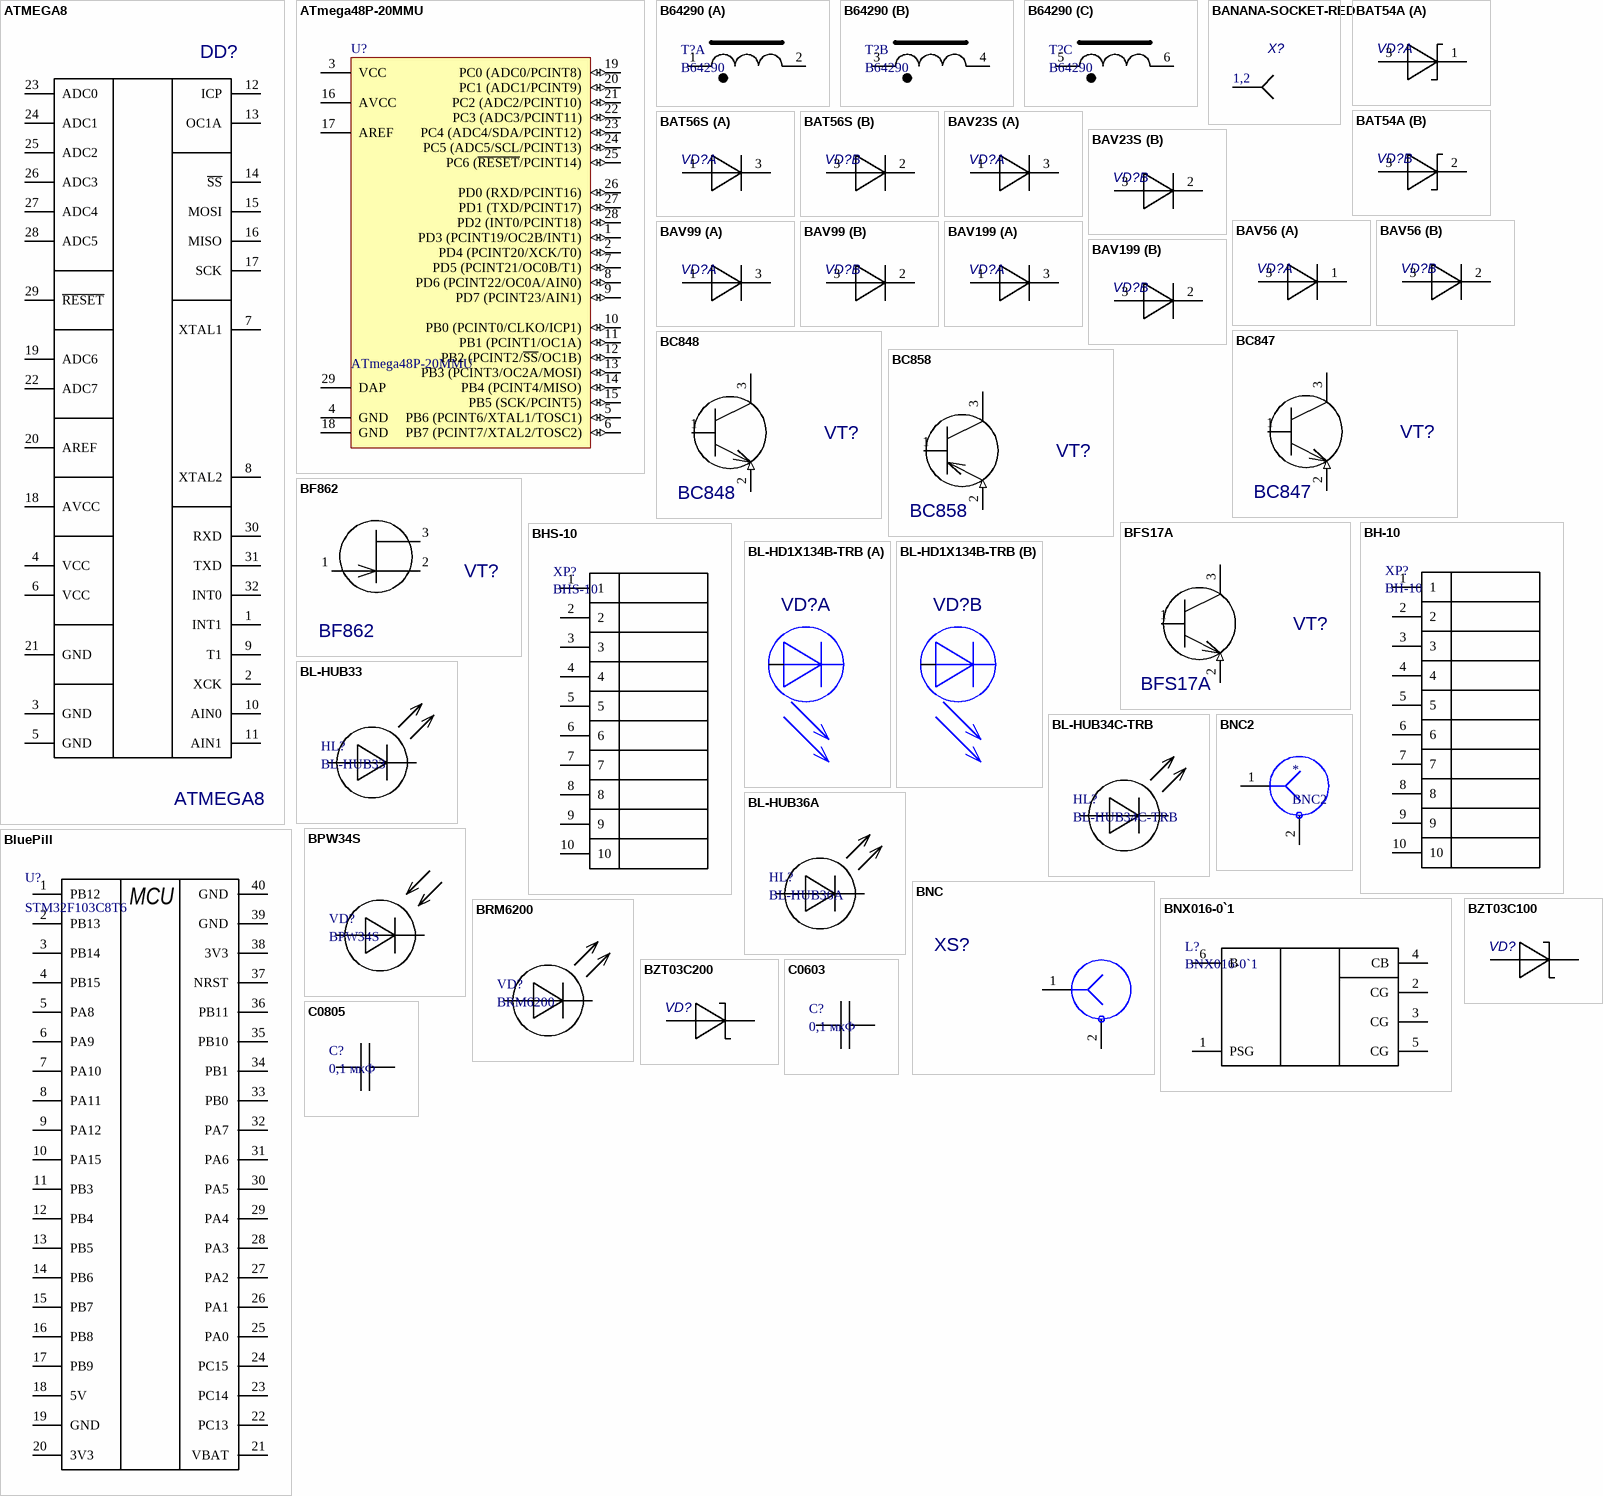
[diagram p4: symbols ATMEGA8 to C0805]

## ATMEGA8
designator DD?
footprint 32A_L (32-Pin Thin Quad Flat Pack 0.8 mm Pitch, IPC High Density)
pins: 1 INT1, 2 XCK, 3 GND, 4 VCC, 5 GND, 6 VCC, 7 XTAL1, 8 XTAL2, 9 T1, 10 AIN0, 11 AIN1, 12 ICP, 13 OC1A, 14 ~{SS}, 15 MOSI, 16 MISO, 17 SCK, 18 AVCC, 19 ADC6, 20 AREF, 21 GND, 22 ADC7, 23 ADC0, 24 ADC1, 25 ADC2, 26 ADC3, 27 ADC4, 28 ADC5, 29 ~{RESET}, 30 RXD, 31 TXD, 32 INT0

## ATmega48P-20MMU
designator U?
8-bit AVR Microcontroller, picoPower, 2.7-5.5V, 4KB Flash, 256 Bytes EEPROM, 512 Bytes SRAM, 28-pin VQFN, Industrial Grade (-40°C to 85°C)
footprint 28M1_N (QFN, 28-Leads, Body 4x4mm, Pitch 0.45mm, Thermal Pad 2.5x2.5mm, IPC Medium Density)
footprint 28M1_L (QFN, 28-Leads, Body 4x4mm, Pitch 0.45mm, Thermal Pad 2.5x2.5mm, IPC High Density)
footprint 28M1_M (QFN, 28-Leads, Body 4x4mm, Pitch 0.45mm, Thermal Pad 2.5x2.5mm, IPC Low Density)
pins: 1 PD3 (PCINT19/OC2B/INT1) (io), 2 PD4 (PCINT20/XCK/T0) (io), 3 VCC (power), 4 GND (power), 5 PB6 (PCINT6/XTAL1/TOSC1) (io), 6 PB7 (PCINT7/XTAL2/TOSC2) (io), 7 PD5 (PCINT21/OC0B/T1) (io), 8 PD6 (PCINT22/OC0A/AIN0) (io), 9 PD7 (PCINT23/AIN1) (io), 10 PB0 (PCINT0/CLKO/ICP1) (io), 11 PB1 (PCINT1/OC1A) (io), 12 PB2 (PCINT2/~{SS}/OC1B) (io), 13 PB3 (PCINT3/OC2A/MOSI) (io), 14 PB4 (PCINT4/MISO) (io), 15 PB5 (SCK/PCINT5) (io), 16 AVCC (power), 17 AREF (power), 18 GND (power), 19 PC0 (ADC0/PCINT8) (io), 20 PC1 (ADC1/PCINT9) (io), 21 PC2 (ADC2/PCINT10) (io), 22 PC3 (ADC3/PCINT11) (io), 23 PC4 (ADC4/SDA/PCINT12) (io), 24 PC5 (ADC5/SCL/PCINT13) (io), 25 PC6 (~{RESET}/PCINT14) (io), 26 PD0 (RXD/PCINT16) (io), 27 PD1 (TXD/PCINT17) (io), 28 PD2 (INT0/PCINT18) (io), 29 DAP (power)

## B64290
designator T?
footprint B64290 (Трансформатор для дозиметра)
part A pins: 1, 2
part B pins: 3, 4
part C pins: 5, 6

## BANANA-SOCKET-RED
designator X?  (value not drawn)
footprint BANANA-SOCKET-RED
pins: 1, 2

## BAT54A
designator VD?  (value not drawn)
Silicon Switching Diode Array for High-Speed Switching
footprint SOT23-3L (SOT23, 3-Leads, Body 2.9x1.3mm, Pitch 0.95mm, Lead Span 2.5mm, IPC High Density)
part A pins: 1 C, 3 A
part B pins: 2 C, 3 A

## BAT56S
designator VD?  (value not drawn)
Silicon Switching Diode Array for High-Speed Switching
simulation model BAV99 (SUBCKT)
footprint SOT23-3L (SOT23, 3-Leads, Body 2.9x1.3mm, Pitch 0.95mm, Lead Span 2.5mm, IPC High Density)
part A pins: 1 A, 3 C
part B pins: 2 K, 3 C

## BAV23S
designator VD?  (value not drawn)
Silicon Switching Diode Array for High-Speed Switching
simulation model BAV99 (SUBCKT)
footprint SOT23-3L (SOT23, 3-Leads, Body 2.9x1.3mm, Pitch 0.95mm, Lead Span 2.5mm, IPC High Density)
part A pins: 1 A, 3 C
part B pins: 2 K, 3 C

## BAV56
designator VD?  (value not drawn)
Silicon Switching Diode Array for High-Speed Switching
footprint SOT23-3L (SOT23, 3-Leads, Body 2.9x1.3mm, Pitch 0.95mm, Lead Span 2.5mm, IPC High Density)
part A pins: 1 C, 3 A
part B pins: 2 C, 3 A

## BAV99
designator VD?  (value not drawn)
Silicon Switching Diode Array for High-Speed Switching
simulation model BAV99 (SUBCKT)
footprint SOT23-3L (SOT23, 3-Leads, Body 2.9x1.3mm, Pitch 0.95mm, Lead Span 2.5mm, IPC High Density)
part A pins: 1 A, 3 C
part B pins: 2 K, 3 C

## BAV199
designator VD?  (value not drawn)
Silicon Switching Diode Array for High-Speed Switching
footprint SOT23-3L (SOT23, 3-Leads, Body 2.9x1.3mm, Pitch 0.95mm, Lead Span 2.5mm, IPC High Density)
part A pins: 1 A, 3 C
part B pins: 2 K, 3 C

## BC847
designator VT?
footprint SOT23-3L (SOT23, 3-Leads, Body 2.9x1.3mm, Pitch 0.95mm, Lead Span 2.5mm, IPC High Density)
pins: 1 BASE (oc), 2 EMIT (in), 3 COLLEC (oe)

## BC848
designator VT?
PDIF_TY: 89; PDIF_I_PID: KT3102
footprint SOT23-3L (SOT23, 3-Leads, Body 2.9x1.3mm, Pitch 0.95mm, Lead Span 2.5mm, IPC High Density)
pins: 1 BASE (oc), 2 EMIT (in), 3 COLLEC (oe)

## BC858
designator VT?
footprint SOT23-3L (SOT23, 3-Leads, Body 2.9x1.3mm, Pitch 0.95mm, Lead Span 2.5mm, IPC High Density)
pins: 1 BASE (oc), 2 EMIT (in), 3 COLLEC (oe)

## BF862
designator VT?
N-CHANEL-FET
footprint SOT23-3L (SOT23, 3-Leads, Body 2.9x1.3mm, Pitch 0.95mm, Lead Span 2.5mm, IPC High Density)
pins: 1, 2, 3

## BFS17A
designator VT?
footprint SOT23-3L (SOT23, 3-Leads, Body 2.9x1.3mm, Pitch 0.95mm, Lead Span 2.5mm, IPC High Density)
pins: 1 BASE (oc), 2 EMIT (in), 3 COLLEC (oe)

## BH-10
designator XP?
footprint BH-10 (Connector; IDC, Low Profile Male Header, Thru-Hole; 10 Position; Vertical; Pitch 2.54 mm; Body 20.32 x 9.2 x 9.45 mm (LxWxH))
pins: 1, 2, 3, 4, 5, 6, 7, 8, 9, 10

## BHS-10
designator XP?
footprint BHS-10
pins: 1, 2, 3, 4, 5, 6, 7, 8, 9, 10

## BL-HD1X134B-TRB
designator VD?  (value not drawn)
footprint BL-HD1X134B-TRB
pins on every part: 3 ANOD
part A pins: 1 CATODE
part B pins: 2 CATODE

## BL-HUB33
designator HL?
Red LED SMD1206
footprint DIOM3216X11N (Molded Diode, 2-Leads, Body 3,20x1,60mm, IPC Medium Density)
pins: 1 A, 2 C

## BL-HUB34C-TRB
designator HL?
Red LED SMD1206
footprint BL-HUB34C-TRB
pins: 1 C, 3 A

## BL-HUB36A
designator HL?
Red LED SMD0603
footprint LED0603
pins: 1 A, 2 C

## BluePill
designator U?, comment STM32F103C8T6
Designed By @Alixahedi
footprint Stm32 BluePill
pins: 1 PB12, 2 PB13, 3 PB14, 4 PB15, 5 PA8, 6 PA9, 7 PA10, 8 PA11, 9 PA12, 10 PA15, 11 PB3, 12 PB4, 13 PB5, 14 PB6, 15 PB7, 16 PB8, 17 PB9, 18 5V, 19 GND, 20 3V3, 21 VBAT, 22 PC13, 23 PC14, 24 PC15, 25 PA0, 26 PA1, 27 PA2, 28 PA3, 29 PA4, 30 PA5, 31 PA6, 32 PA7, 33 PB0, 34 PB1, 35 PB10, 36 PB11, 37 NRST, 38 3V3, 39 GND, 40 GND

## BNC
designator XS?  (value not drawn)
PDIF_TY: 13000; PDIF_I_PID: BNC.SYM
footprint BNC
pins: 1, 2, 3 hidden, 4 hidden

## BNC2
designator *
footprint BNC2
pins: 1, 2

## BNX016-0`1
designator L?
footprint BNC016-01 (Low profile version)
pins: 1 PSG, 2 CG, 3 CG, 4 CB, 5 CG, 6 B

## BPW34S
designator VD?
Silicon PIN Photodiode
footprint DIOM4439X12N (Molded Diode, 2-Leads, Body 4,40x3,85mm, IPC Medium Density)
pins: 1 A, 2 C

## BRM6200
designator VD?
footprint BRM6200
pins: 1 A, 2 C

## BZT03C100
designator VD?  (value not drawn)
Silicon Switching Diode Array for High-Speed Switching
footprint BZT03C100
pins: 1 A, 2 C

## BZT03C200
designator VD?  (value not drawn)
Silicon Switching Diode Array for High-Speed Switching
footprint BZT03C200
pins: 1 A, 2 C

## C0603
designator C?, comment 0,1 мкФ
планарный конденсатор
footprint C0603
pins: 1, 2

## C0805
designator C?, comment 0,1 мкФ
планарный конденсатор
footprint CAPC2012L-С0805 (Chip Capacitor, Body 2.0x1.3mm, IPC High Density)
pins: 1, 2

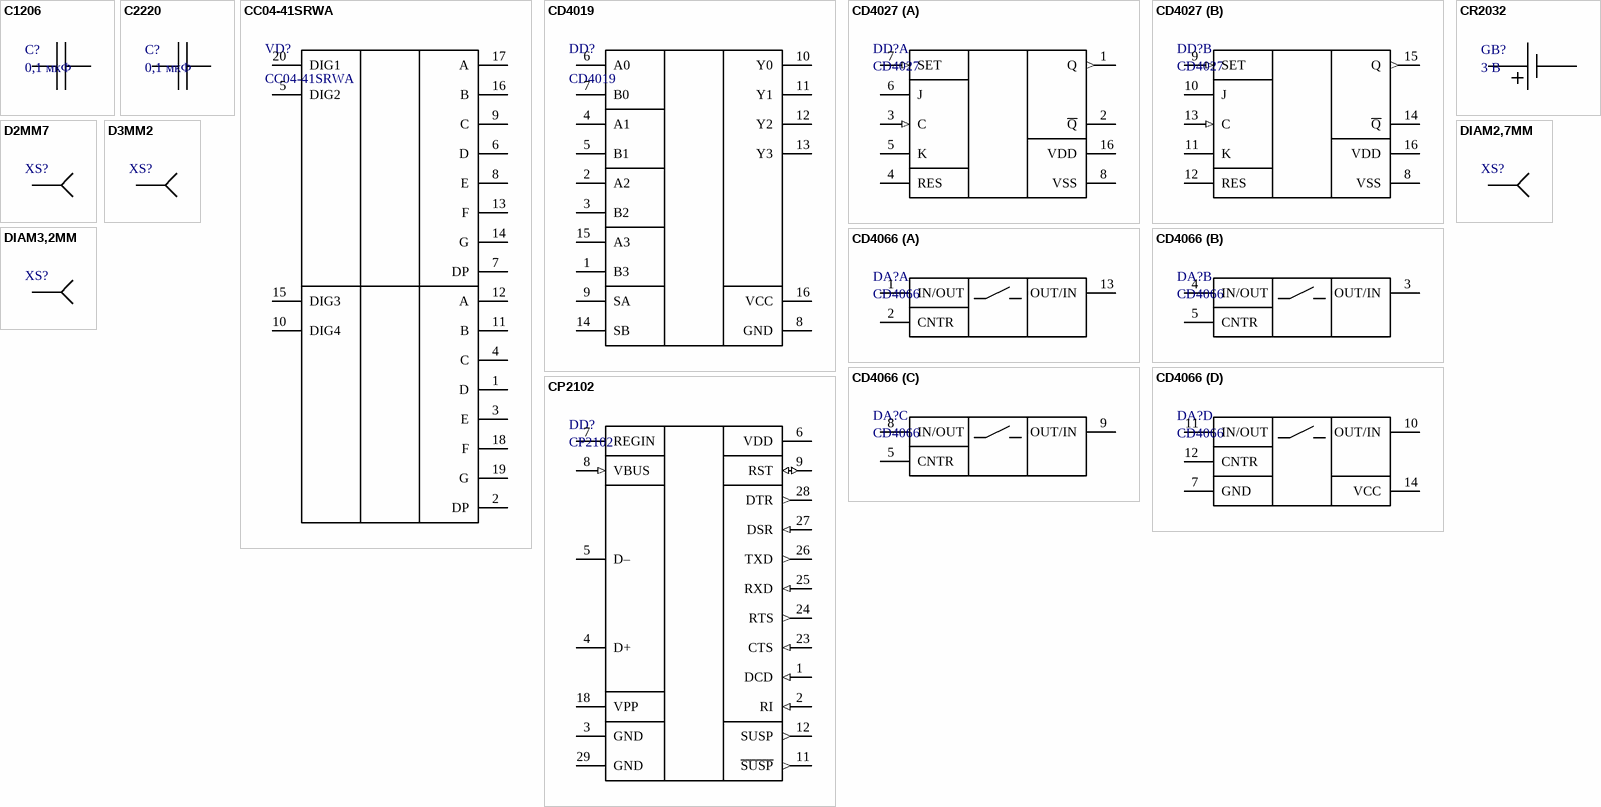
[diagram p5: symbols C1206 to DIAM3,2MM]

## C1206
designator C?, comment 0,1 мкФ
планарный конденсатор
footprint C1206
pins: 1, 2

## C2220
designator C?, comment 0,1 мкФ
планарный конденсатор
footprint CAPC5750L (Chip Capacitor, Body 5.7x5.0mm, IPC High Density)
pins: 1, 2

## CC04-41SRWA
designator VD?
FOUR DIGIT NUMERIC  DISPLAY
footprint CC04-41SRWA
pins: 1 D, 2 DP, 3 E, 4 C, 5 DIG2, 6 D, 7 DP, 8 E, 9 C, 10 DIG4, 11 B, 12 A, 13 F, 14 G, 15 DIG3, 16 B, 17 A, 18 F, 19 G, 20 DIG1

## CD4019
designator DD?
footprint R-16A_M (16-Pin Small Outline Integrated Circuit 1.27 mm Pitch, IPC Low Density)
pins: 1 B3, 2 A2, 3 B2, 4 A1, 5 B1, 6 A0, 7 B0, 8 GND, 9 SA, 10 Y0, 11 Y1, 12 Y2, 13 Y3, 14 SB, 15 A3, 16 VCC

## CD4027
designator DD?
2X-JK-TRIGGER
footprint R-16A_M (16-Pin Small Outline Integrated Circuit 1.27 mm Pitch, IPC Low Density)
part A pins: 1 Q (out), 2 ~{Q}, 3 C (in), 4 RES, 5 K, 6 J, 7 SET (in), 8 VSS (power), 16 VDD (power)
part B pins: 8 VSS (power), 9 SET (in), 10 J, 11 K, 12 RES, 13 C (in), 14 ~{Q}, 15 Q (out), 16 VDD (power)

## CD4066
designator DA?
footprint R-14_M (14-Pin Narrow Body Small Outline Integrated Circuit 1.27 mm Pitch, IPC Low Density)
part A pins: 1 IN/OUT, 2 CNTR, 13 OUT/IN
part B pins: 3 OUT/IN, 4 IN/OUT, 5 CNTR
part C pins: 5 CNTR, 8 IN/OUT, 9 OUT/IN
part D pins: 7 GND, 10 OUT/IN, 11 IN/OUT, 12 CNTR, 14 VCC

## CP2102
designator DD?
footprint QFN50P500X500-28V1N (QFN, 28-Leads, Body 5x5mm, Pitch 0.5mm, IPC Medium Density)
pins: 1 DCD (in), 2 RI (in), 3 GND (power), 4 D+, 5 D–, 6 VDD (power), 7 REGIN (power), 8 VBUS (in), 9 RST (io), 11 ~{SUSP} (out), 12 SUSP (out), 18 VPP (power), 23 CTS (in), 24 RTS (out), 25 RXD (in), 26 TXD (out), 27 DSR (in), 28 DTR (out), 29 GND (power)

## CR2032
designator GB?, comment 3 В
Литиевый элемент
footprint CR2035
pins: 1 +, 2 +, 3 -

## D2MM7
designator XS?  (value not drawn)
KlemmaD1
footprint D2MM7
pins: 0

## D3MM2
designator XS?  (value not drawn)
footprint D3MM2
pins: 1

## DIAM2,7MM
designator XS?  (value not drawn)
footprint DIAM2,7MM
pins: 1

## DIAM3,2MM
designator XS?  (value not drawn)
footprint DIAM3,2MM
pins: 1

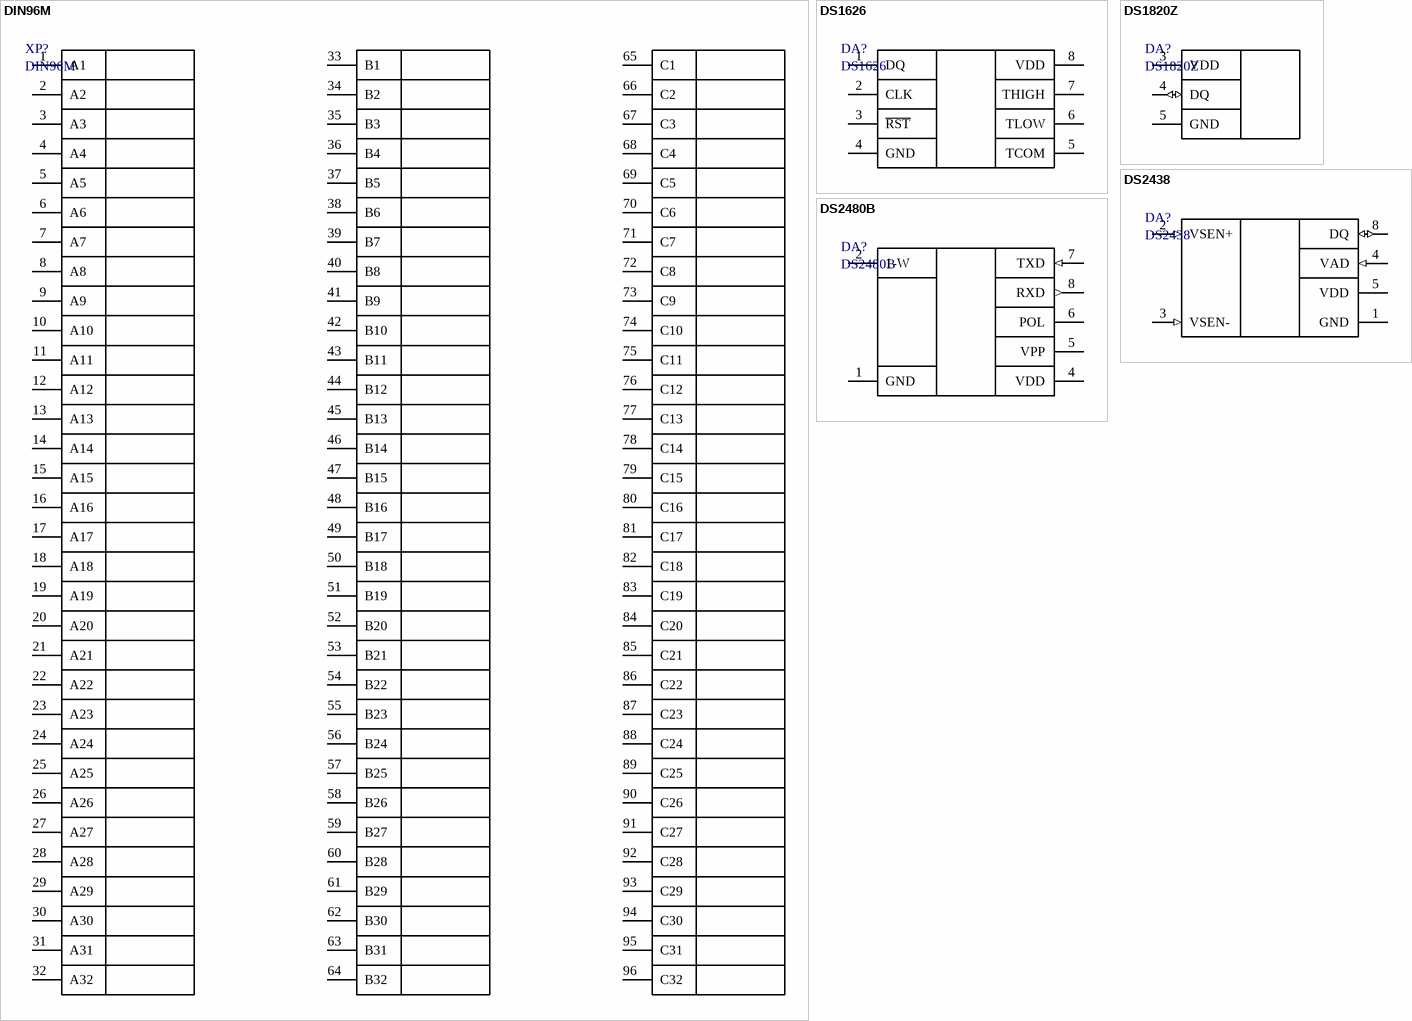
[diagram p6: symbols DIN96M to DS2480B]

## DIN96M
designator XP?
footprint DIN96M
pins: 1 A1, 2 A2, 3 A3, 4 A4, 5 A5, 6 A6, 7 A7, 8 A8, 9 A9, 10 A10, 11 A11, 12 A12, 13 A13, 14 A14, 15 A15, 16 A16, 17 A17, 18 A18, 19 A19, 20 A20, 21 A21, 22 A22, 23 A23, 24 A24, 25 A25, 26 A26, 27 A27, 28 A28, 29 A29, 30 A30, 31 A31, 32 A32, 33 B1, 34 B2, 35 B3, 36 B4, 37 B5, 38 B6, 39 B7, 40 B8, 41 B9, 42 B10, 43 B11, 44 B12, 45 B13, 46 B14, 47 B15, 48 B16, 49 B17, 50 B18, 51 B19, 52 B20, 53 B21, 54 B22, 55 B23, 56 B24, 57 B25, 58 B26, 59 B27, 60 B28, 61 B29, 62 B30, 63 B31, 64 B32, 65 C1, 66 C2, 67 C3, 68 C4, 69 C5, 70 C6, 71 C7, 72 C8, 73 C9, 74 C10, 75 C11, 76 C12, 77 C13, 78 C14, 79 C15, 80 C16, 81 C17, 82 C18, 83 C19, 84 C20, 85 C21, 86 C22, 87 C23, 88 C24, 89 C25, 90 C26, 91 C27, 92 C28, 93 C29, 94 C30, 95 C31, 96 C32

## DS1626
designator DA?
High-Precision 3-Wire Digital  Thermometer and Thermostat
footprint UMAX8 (Shrink Small Outline; 8 Leads; Body Width 3 mm; Pitch 0.65 mm)
pins: 1 DQ (power), 2 CLK, 3 ~{RST}, 4 GND (power), 5 TCOM (power), 6 TLOW, 7 THIGH, 8 VDD

## DS1820Z
designator DA?
footprint SOIC127P600-8BM (SOIC, 8-Leads, Body 4.9x3.9mm, Pitch 1.27mm, IPC Low Density)
pins: 3 VDD (power), 4 DQ (io), 5 GND (power)

## DS2438
designator DA?
Smart Battery Monitor
footprint SOIC_N_EP (8-Pin Small Outline Integrated Circuit 1.27 mm Pitch, IPC High Density)
pins: 1 GND (power), 2 VSEN+ (in), 3 VSEN- (in), 4 VAD (in), 5 VDD (power), 8 DQ (io)

## DS2480B
designator DA?
footprint SOIC127P600-8BM (SOIC, 8-Leads, Body 4.9x3.9mm, Pitch 1.27mm, IPC Low Density)
pins: 1 GND (power), 2 1-W, 4 VDD (power), 5 VPP (power), 6 POL, 7 TXD (in), 8 RXD (out)

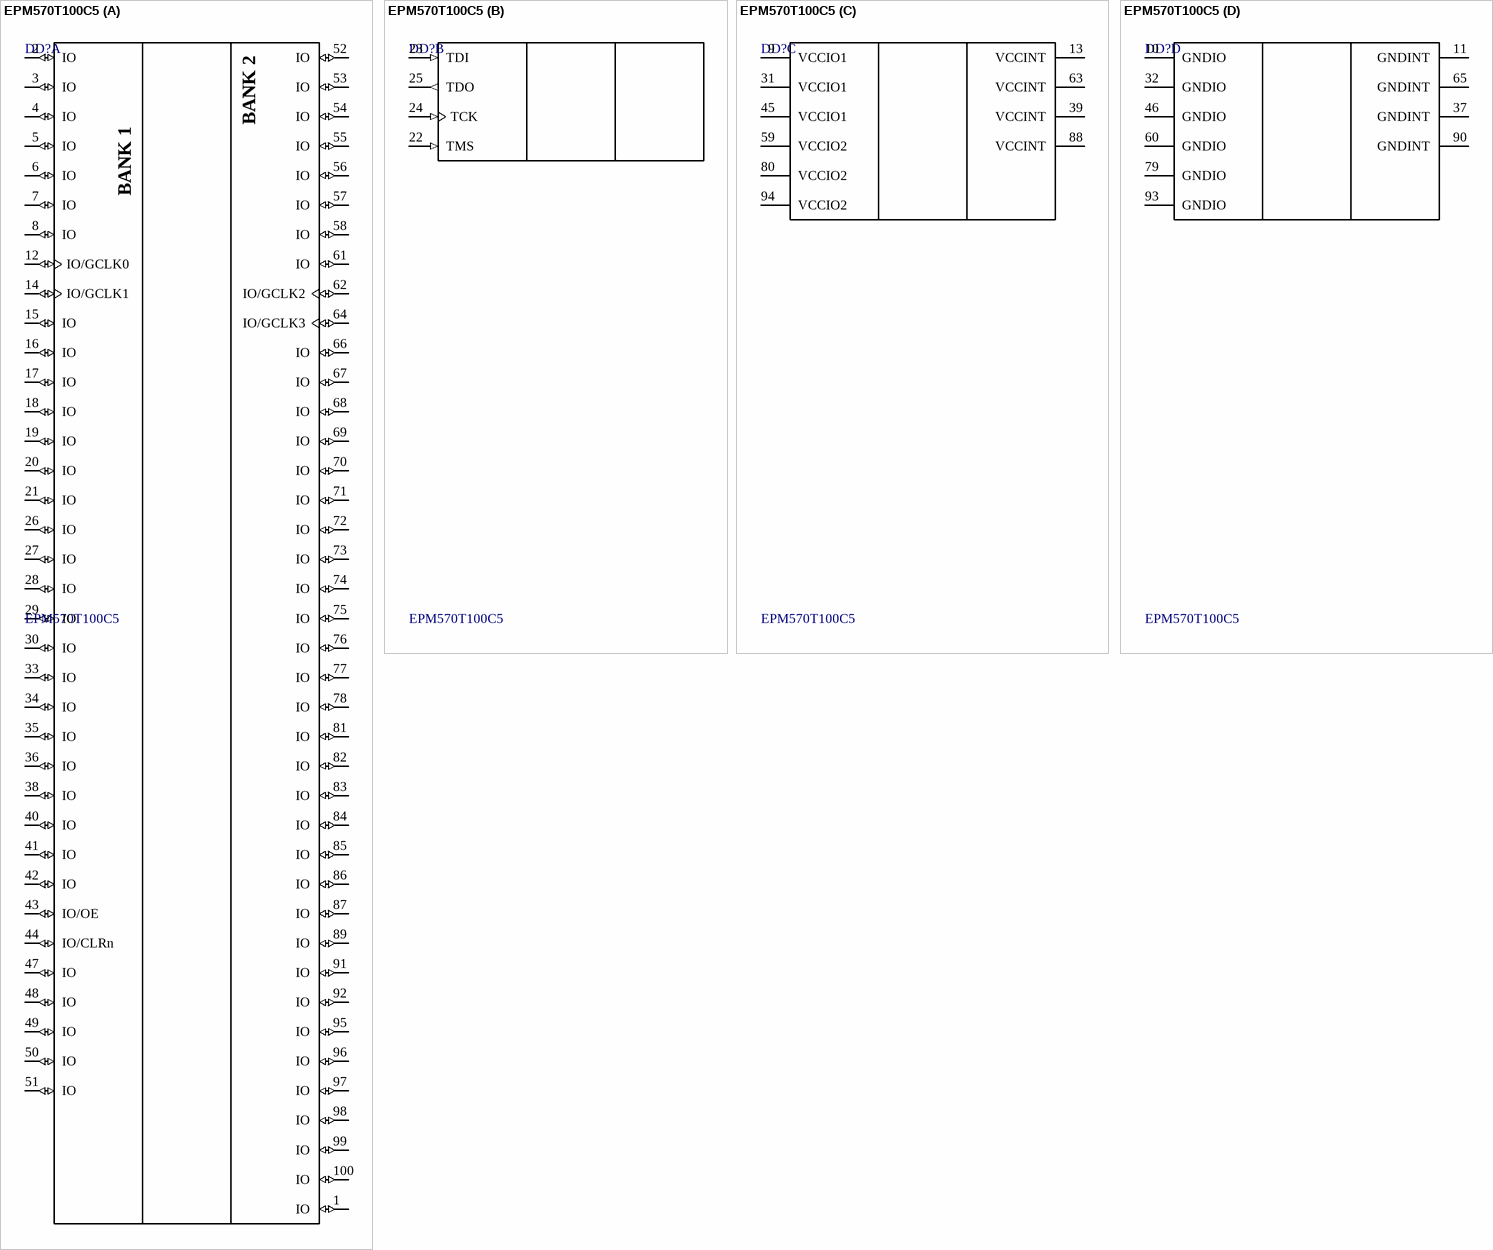
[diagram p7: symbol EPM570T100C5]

## EPM570T100C5
designator DD?
MAX II 3.3/2.5V CPLD, 76 IOs, 570 Logic Elements, 100-Pin Plastic TQFP, Commercial Temperature, Speed Grade 5; Note: All VCCINT pins must be connected to either 3.3V or 2.5V (but not a combination of both).
footprint TQFP100_N (Thin QFP, 100-Leads, Body 14x14mm, Pitch 0.5mm, IPC Medium Density)
part A pins: 1 IO (io), 2 IO (io), 3 IO (io), 4 IO (io), 5 IO (io), 6 IO (io), 7 IO (io), 8 IO (io), 12 IO/GCLK0 (io), 14 IO/GCLK1 (io), 15 IO (io), 16 IO (io), 17 IO (io), 18 IO (io), 19 IO (io), 20 IO (io), 21 IO (io), 26 IO (io), 27 IO (io), 28 IO (io), 29 IO (io), 30 IO (io), 33 IO (io), 34 IO (io), 35 IO (io), 36 IO (io), 38 IO (io), 40 IO (io), 41 IO (io), 42 IO (io), 43 IO/OE (io), 44 IO/CLRn (io), 47 IO (io), 48 IO (io), 49 IO (io), 50 IO (io), 51 IO (io), 52 IO (io), 53 IO (io), 54 IO (io), 55 IO (io), 56 IO (io), 57 IO (io), 58 IO (io), 61 IO (io), 62 IO/GCLK2 (io), 64 IO/GCLK3 (io), 66 IO (io), 67 IO (io), 68 IO (io), 69 IO (io), 70 IO (io), 71 IO (io), 72 IO (io), 73 IO (io), 74 IO (io), 75 IO (io), 76 IO (io), 77 IO (io), 78 IO (io), 81 IO (io), 82 IO (io), 83 IO (io), 84 IO (io), 85 IO (io), 86 IO (io), 87 IO (io), 89 IO (io), 91 IO (io), 92 IO (io), 95 IO (io), 96 IO (io), 97 IO (io), 98 IO (io), 99 IO (io), 100 IO (io)
part B pins: 22 TMS (in), 23 TDI (in), 24 TCK (in), 25 TDO (out)
part C pins: 9 VCCIO1 (power), 13 VCCINT (power), 31 VCCIO1 (power), 39 VCCINT (power), 45 VCCIO1 (power), 59 VCCIO2 (power), 63 VCCINT (power), 80 VCCIO2 (power), 88 VCCINT (power), 94 VCCIO2 (power)
part D pins: 10 GNDIO (power), 11 GNDINT (power), 32 GNDIO (power), 37 GNDINT (power), 46 GNDIO (power), 60 GNDIO (power), 65 GNDINT (power), 79 GNDIO (power), 90 GNDINT (power), 93 GNDIO (power)

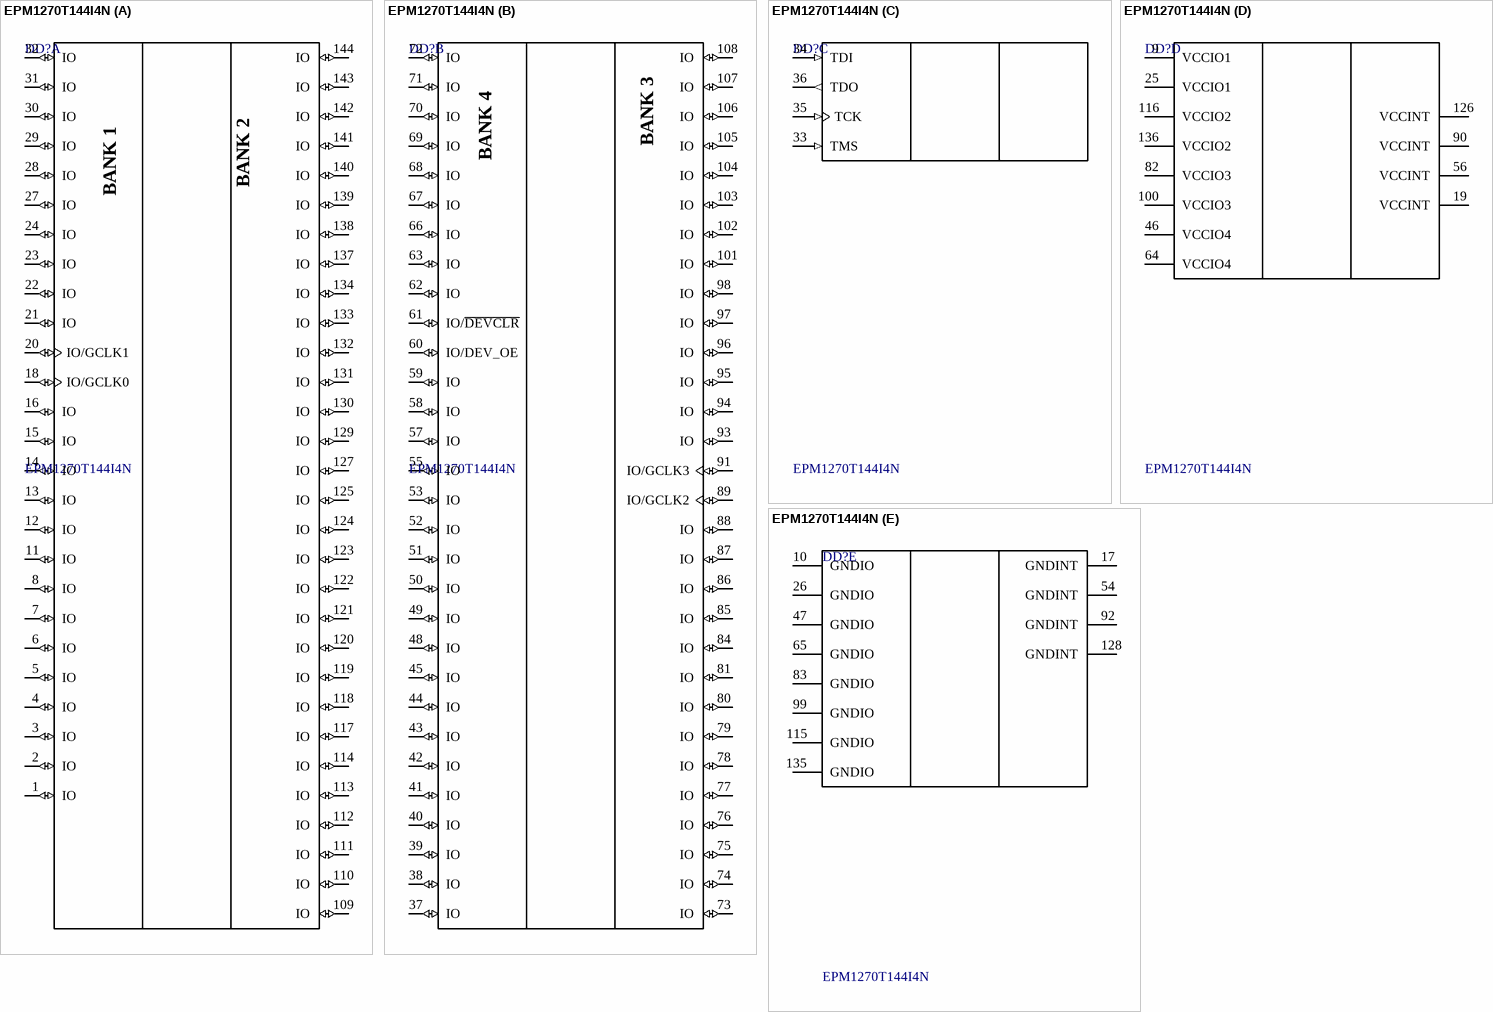
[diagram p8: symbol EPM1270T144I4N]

## EPM1270T144I4N
designator DD?
MAX II 3.3/2.5V CPLD, 116 IOs, 1,270 Logic Elements, 144-Pin Plastic TQFP, Industrial Temperature, Speed Grade 4, Pb-Free; Note: All VCCINT pins must be connected to either 3.3V or 2.5V (but not a combination of both).
footprint TQFP144_N (Thin QFP, 144-Leads, Body 20x20mm, Pitch 0.5mm, IPC Medium Density)
footprint TQFP144_L (Thin QFP, 144-Leads, Body 20x20mm, Pitch 0.5mm, IPC High Density)
footprint TQFP144_M (Thin QFP, 144-Leads, Body 20x20mm, Pitch 0.5mm, IPC Low Density)
part A pins: 1 IO (io), 2 IO (io), 3 IO (io), 4 IO (io), 5 IO (io), 6 IO (io), 7 IO (io), 8 IO (io), 11 IO (io), 12 IO (io), 13 IO (io), 14 IO (io), 15 IO (io), 16 IO (io), 18 IO/GCLK0 (io), 20 IO/GCLK1 (io), 21 IO (io), 22 IO (io), 23 IO (io), 24 IO (io), 27 IO (io), 28 IO (io), 29 IO (io), 30 IO (io), 31 IO (io), 32 IO (io), 109 IO (io), 110 IO (io), 111 IO (io), 112 IO (io), 113 IO (io), 114 IO (io), 117 IO (io), 118 IO (io), 119 IO (io), 120 IO (io), 121 IO (io), 122 IO (io), 123 IO (io), 124 IO (io), 125 IO (io), 127 IO (io), 129 IO (io), 130 IO (io), 131 IO (io), 132 IO (io), 133 IO (io), 134 IO (io), 137 IO (io), 138 IO (io), 139 IO (io), 140 IO (io), 141 IO (io), 142 IO (io), 143 IO (io), 144 IO (io)
part B pins: 37 IO (io), 38 IO (io), 39 IO (io), 40 IO (io), 41 IO (io), 42 IO (io), 43 IO (io), 44 IO (io), 45 IO (io), 48 IO (io), 49 IO (io), 50 IO (io), 51 IO (io), 52 IO (io), 53 IO (io), 55 IO (io), 57 IO (io), 58 IO (io), 59 IO (io), 60 IO/DEV_OE (io), 61 IO/~{DEVCLR} (io), 62 IO (io), 63 IO (io), 66 IO (io), 67 IO (io), 68 IO (io), 69 IO (io), 70 IO (io), 71 IO (io), 72 IO (io), 73 IO (io), 74 IO (io), 75 IO (io), 76 IO (io), 77 IO (io), 78 IO (io), 79 IO (io), 80 IO (io), 81 IO (io), 84 IO (io), 85 IO (io), 86 IO (io), 87 IO (io), 88 IO (io), 89 IO/GCLK2 (io), 91 IO/GCLK3 (io), 93 IO (io), 94 IO (io), 95 IO (io), 96 IO (io), 97 IO (io), 98 IO (io), 101 IO (io), 102 IO (io), 103 IO (io), 104 IO (io), 105 IO (io), 106 IO (io), 107 IO (io), 108 IO (io)
part C pins: 33 TMS (in), 34 TDI (in), 35 TCK (in), 36 TDO (out)
part D pins: 9 VCCIO1 (power), 19 VCCINT (power), 25 VCCIO1 (power), 46 VCCIO4 (power), 56 VCCINT (power), 64 VCCIO4 (power), 82 VCCIO3 (power), 90 VCCINT (power), 100 VCCIO3 (power), 116 VCCIO2 (power), 126 VCCINT (power), 136 VCCIO2 (power)
part E pins: 10 GNDIO (power), 17 GNDINT (power), 26 GNDIO (power), 47 GNDIO (power), 54 GNDINT (power), 65 GNDIO (power), 83 GNDIO (power), 92 GNDINT (power), 99 GNDIO (power), 115 GNDIO (power), 128 GNDINT (power), 135 GNDIO (power)

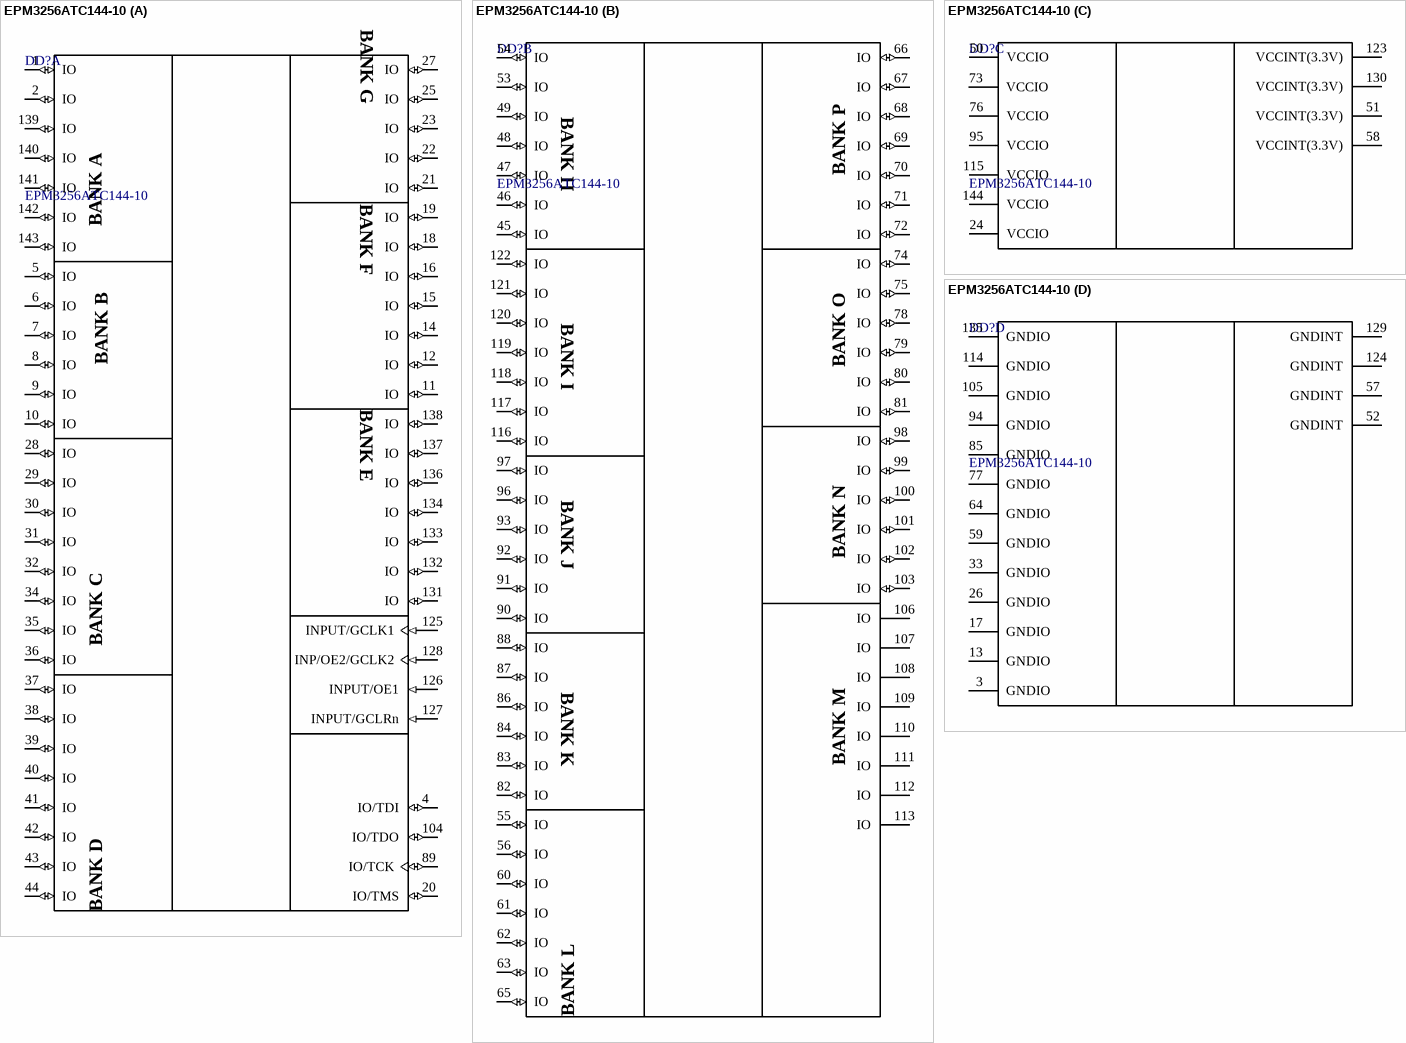
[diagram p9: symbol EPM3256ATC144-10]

## EPM3256ATC144-10
designator DD?
MAX 3256A 3.3V CPLD, 116 IOs, 144-Pin Plastic TQFP, Commercial Temperature, Speed Grade 10
footprint TQFP144_N (Thin QFP, 144-Leads, Body 20x20mm, Pitch 0.5mm, IPC Medium Density)
footprint TQFP144_L (Thin QFP, 144-Leads, Body 20x20mm, Pitch 0.5mm, IPC High Density)
footprint TQFP144_M (Thin QFP, 144-Leads, Body 20x20mm, Pitch 0.5mm, IPC Low Density)
3D model EPM3256A-TQFP144 (144-Pin Plastic Thin Quad Flat Pack (TQFP144) - Wire Bond)
signal-integrity model max3ka (MAX 3000A)
part A pins: 1 IO (io), 2 IO (io), 4 IO/TDI (io), 5 IO (io), 6 IO (io), 7 IO (io), 8 IO (io), 9 IO (io), 10 IO (io), 11 IO (io), 12 IO (io), 14 IO (io), 15 IO (io), 16 IO (io), 18 IO (io), 19 IO (io), 20 IO/TMS (io), 21 IO (io), 22 IO (io), 23 IO (io), 25 IO (io), 27 IO (io), 28 IO (io), 29 IO (io), 30 IO (io), 31 IO (io), 32 IO (io), 34 IO (io), 35 IO (io), 36 IO (io), 37 IO (io), 38 IO (io), 39 IO (io), 40 IO (io), 41 IO (io), 42 IO (io), 43 IO (io), 44 IO (io), 89 IO/TCK (io), 104 IO/TDO (io), 125 INPUT/GCLK1 (in), 126 INPUT/OE1 (in), 127 INPUT/GCLRn (in), 128 INP/OE2/GCLK2 (in), 131 IO (io), 132 IO (io), 133 IO (io), 134 IO (io), 136 IO (io), 137 IO (io), 138 IO (io), 139 IO (io), 140 IO (io), 141 IO (io), 142 IO (io), 143 IO (io)
part B pins: 45 IO (io), 46 IO (io), 47 IO (io), 48 IO (io), 49 IO (io), 53 IO (io), 54 IO (io), 55 IO (io), 56 IO (io), 60 IO (io), 61 IO (io), 62 IO (io), 63 IO (io), 65 IO (io), 66 IO (io), 67 IO (io), 68 IO (io), 69 IO (io), 70 IO (io), 71 IO (io), 72 IO (io), 74 IO (io), 75 IO (io), 78 IO (io), 79 IO (io), 80 IO (io), 81 IO (io), 82 IO (io), 83 IO (io), 84 IO (io), 86 IO (io), 87 IO (io), 88 IO (io), 90 IO (io), 91 IO (io), 92 IO (io), 93 IO (io), 96 IO (io), 97 IO (io), 98 IO (io), 99 IO (io), 100 IO (io), 101 IO (io), 102 IO (io), 103 IO (io), 106 IO, 107 IO, 108 IO, 109 IO, 110 IO, 111 IO, 112 IO, 113 IO, 116 IO (io), 117 IO (io), 118 IO (io), 119 IO (io), 120 IO (io), 121 IO (io), 122 IO (io)
part C pins: 24 VCCIO (power), 50 VCCIO (power), 51 VCCINT(3.3V) (power), 58 VCCINT(3.3V) (power), 73 VCCIO (power), 76 VCCIO (power), 95 VCCIO (power), 115 VCCIO (power), 123 VCCINT(3.3V) (power), 130 VCCINT(3.3V) (power), 144 VCCIO (power)
part D pins: 3 GNDIO (power), 13 GNDIO (power), 17 GNDIO (power), 26 GNDIO (power), 33 GNDIO (power), 52 GNDINT (power), 57 GNDINT (power), 59 GNDIO (power), 64 GNDIO (power), 77 GNDIO (power), 85 GNDIO (power), 94 GNDIO (power), 105 GNDIO (power), 114 GNDIO (power), 124 GNDINT (power), 129 GNDINT (power), 135 GNDIO (power)

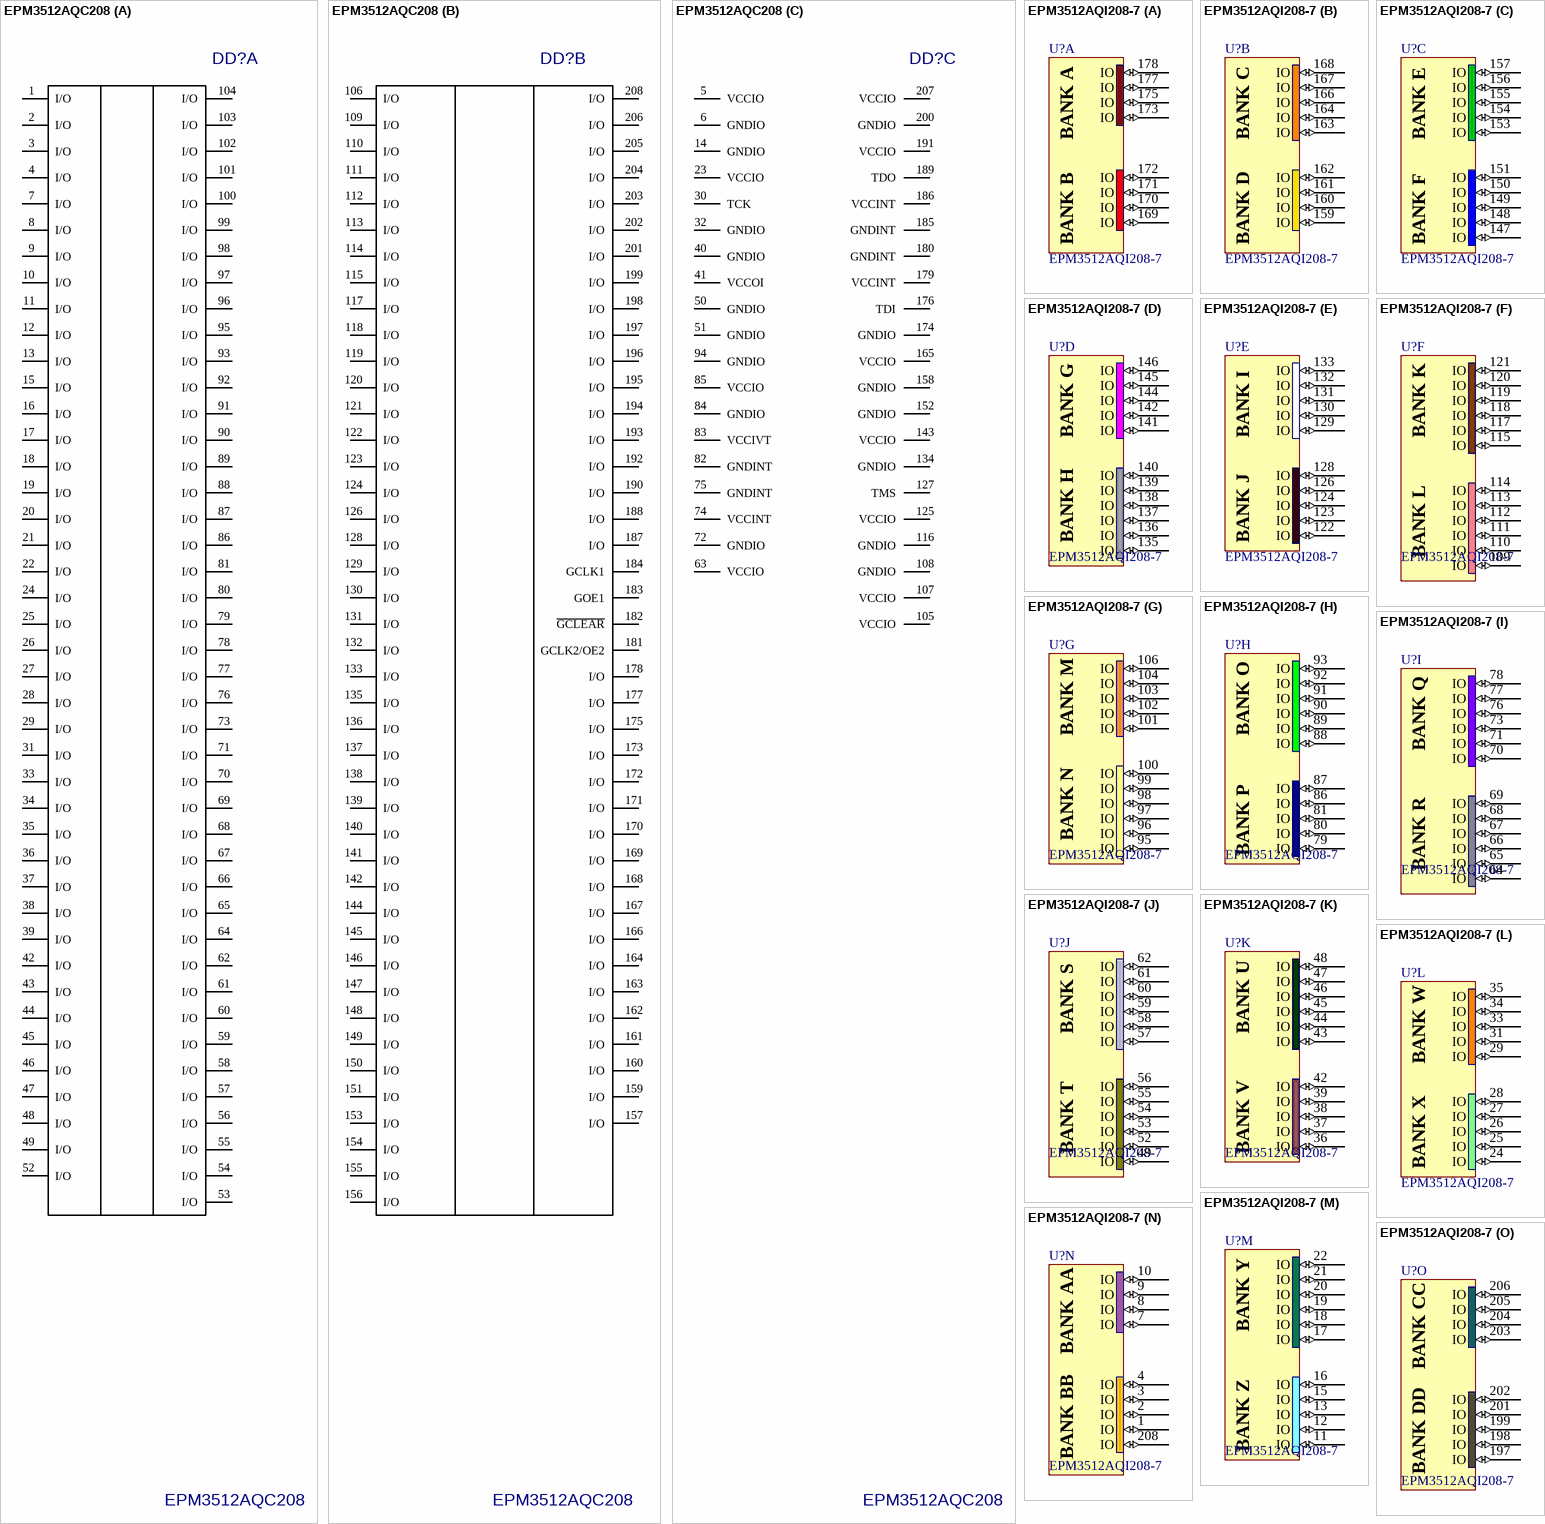
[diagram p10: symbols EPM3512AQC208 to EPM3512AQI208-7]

## EPM3512AQC208
designator DD?
footprint MQFP208
part A pins: 1 I/O, 2 I/O, 3 I/O, 4 I/O, 7 I/O, 8 I/O, 9 I/O, 10 I/O, 11 I/O, 12 I/O, 13 I/O, 15 I/O, 16 I/O, 17 I/O, 18 I/O, 19 I/O, 20 I/O, 21 I/O, 22 I/O, 24 I/O, 25 I/O, 26 I/O, 27 I/O, 28 I/O, 29 I/O, 31 I/O, 33 I/O, 34 I/O, 35 I/O, 36 I/O, 37 I/O, 38 I/O, 39 I/O, 42 I/O, 43 I/O, 44 I/O, 45 I/O, 46 I/O, 47 I/O, 48 I/O, 49 I/O, 52 I/O, 53 I/O, 54 I/O, 55 I/O, 56 I/O, 57 I/O, 58 I/O, 59 I/O, 60 I/O, 61 I/O, 62 I/O, 64 I/O, 65 I/O, 66 I/O, 67 I/O, 68 I/O, 69 I/O, 70 I/O, 71 I/O, 73 I/O, 76 I/O, 77 I/O, 78 I/O, 79 I/O, 80 I/O, 81 I/O, 86 I/O, 87 I/O, 88 I/O, 89 I/O, 90 I/O, 91 I/O, 92 I/O, 93 I/O, 95 I/O, 96 I/O, 97 I/O, 98 I/O, 99 I/O, 100 I/O, 101 I/O, 102 I/O, 103 I/O, 104 I/O
part B pins: 106 I/O, 109 I/O, 110 I/O, 111 I/O, 112 I/O, 113 I/O, 114 I/O, 115 I/O, 117 I/O, 118 I/O, 119 I/O, 120 I/O, 121 I/O, 122 I/O, 123 I/O, 124 I/O, 126 I/O, 128 I/O, 129 I/O, 130 I/O, 131 I/O, 132 I/O, 133 I/O, 135 I/O, 136 I/O, 137 I/O, 138 I/O, 139 I/O, 140 I/O, 141 I/O, 142 I/O, 144 I/O, 145 I/O, 146 I/O, 147 I/O, 148 I/O, 149 I/O, 150 I/O, 151 I/O, 153 I/O, 154 I/O, 155 I/O, 156 I/O, 157 I/O, 159 I/O, 160 I/O, 161 I/O, 162 I/O, 163 I/O, 164 I/O, 166 I/O, 167 I/O, 168 I/O, 169 I/O, 170 I/O, 171 I/O, 172 I/O, 173 I/O, 175 I/O, 177 I/O, 178 I/O, 181 GCLK2/OE2, 182 ~{GCLEAR}, 183 GOE1, 184 GCLK1, 187 I/O, 188 I/O, 190 I/O, 192 I/O, 193 I/O, 194 I/O, 195 I/O, 196 I/O, 197 I/O, 198 I/O, 199 I/O, 201 I/O, 202 I/O, 203 I/O, 204 I/O, 205 I/O, 206 I/O, 208 I/O
part C pins: 5 VCCIO, 6 GNDIO, 14 GNDIO, 23 VCCIO, 30 TCK, 32 GNDIO, 40 GNDIO, 41 VCCOI, 50 GNDIO, 51 GNDIO, 63 VCCIO, 72 GNDIO, 74 VCCINT, 75 GNDINT, 82 GNDINT, 83 VCCIVT, 84 GNDIO, 85 VCCIO, 94 GNDIO, 105 VCCIO, 107 VCCIO, 108 GNDIO, 116 GNDIO, 125 VCCIO, 127 TMS, 134 GNDIO, 143 VCCIO, 152 GNDIO, 158 GNDIO, 165 VCCIO, 174 GNDIO, 176 TDI, 179 VCCINT, 180 GNDINT, 185 GNDINT, 186 VCCINT, 189 TDO, 191 VCCIO, 200 GNDIO, 207 VCCIO

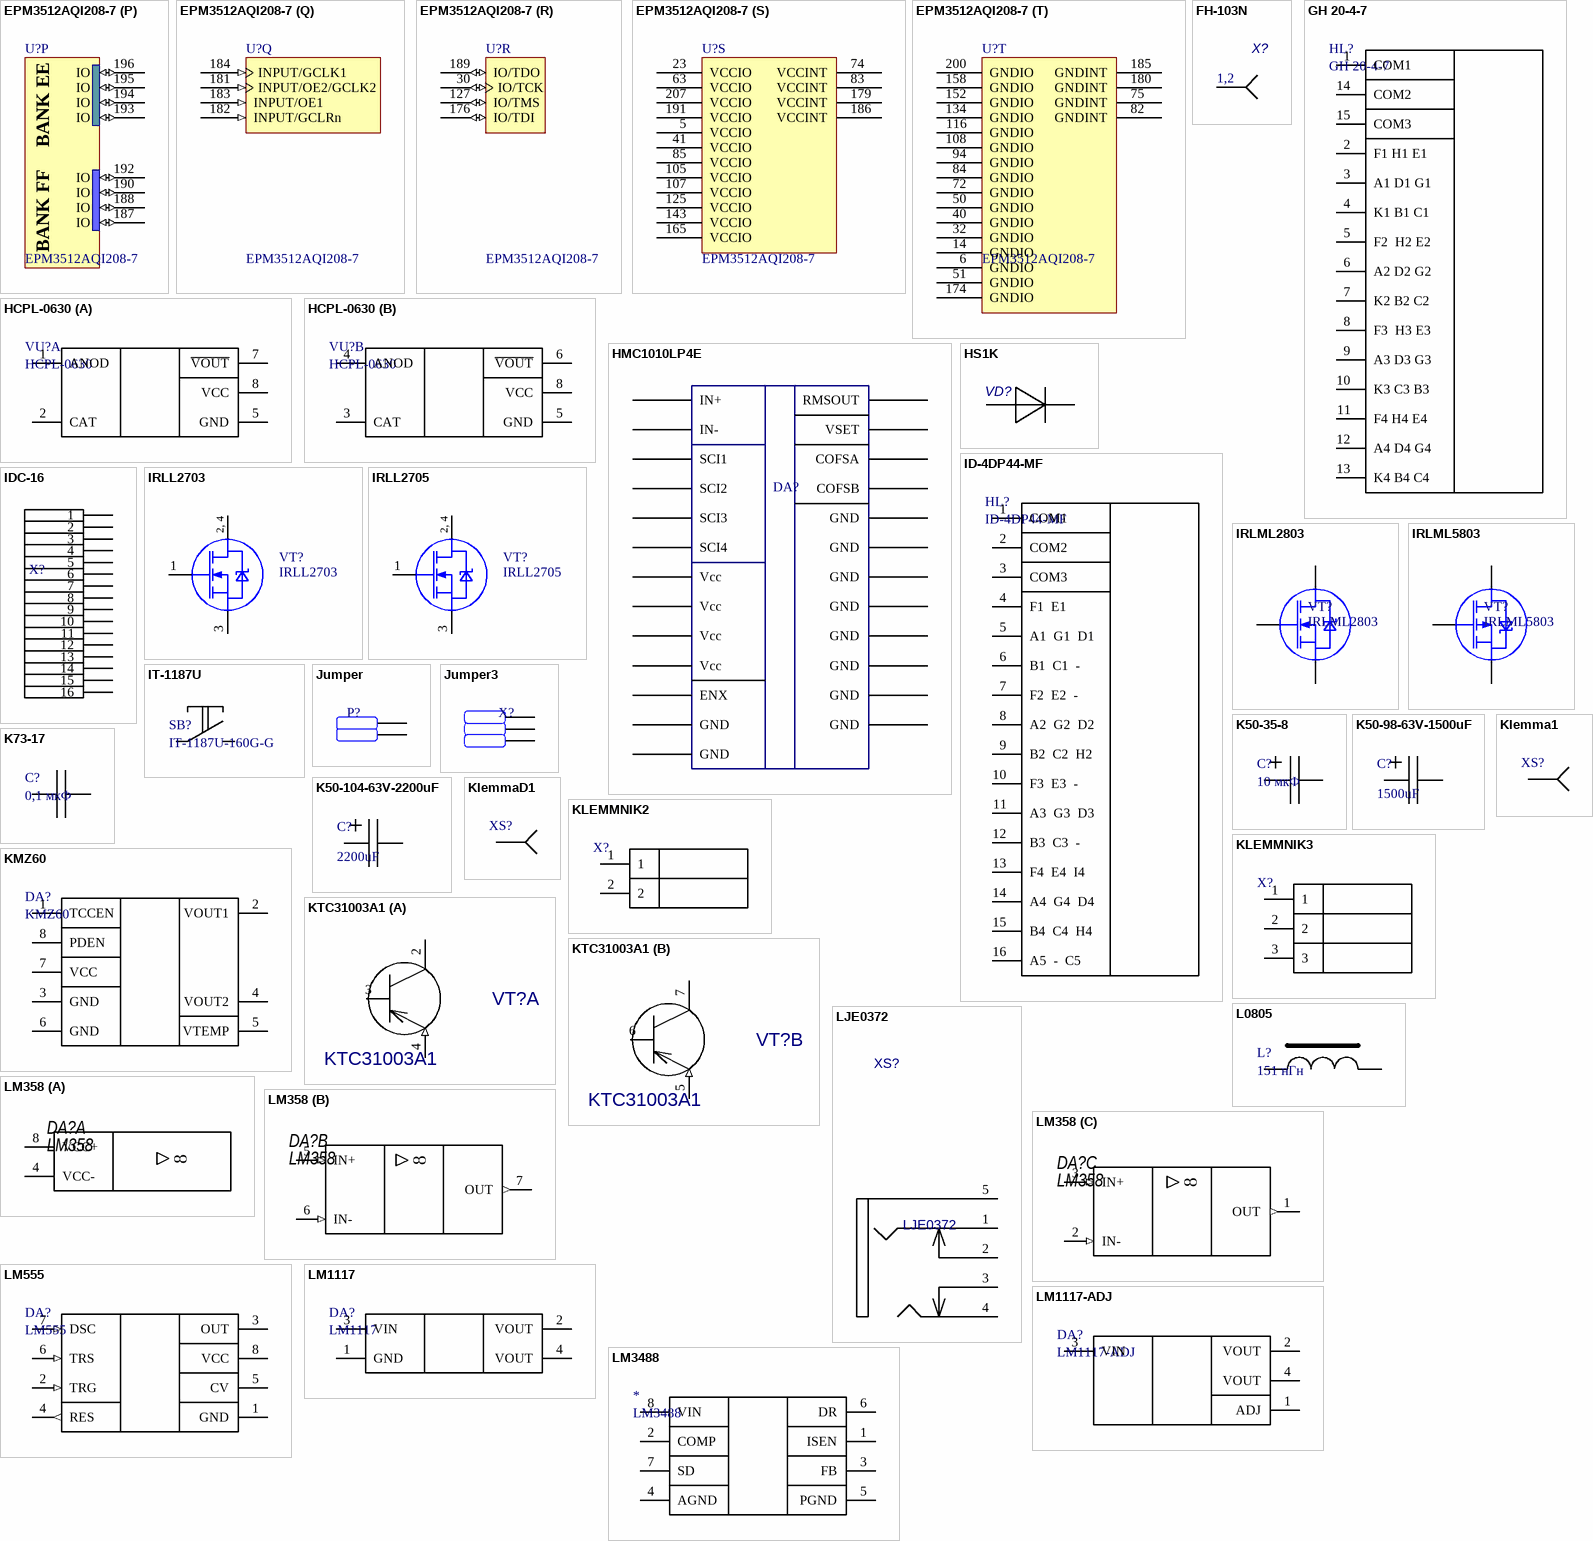
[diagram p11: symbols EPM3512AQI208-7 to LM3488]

## EPM3512AQI208-7
designator U?
MAX 3512A 3.3V CPLD, 172 IOs, 208-Pin PQFP, Industrial Temperature, Speed Grade 7
footprint PQFP208_N (Shrink QFP, 208-Leads, Body 28x28mm, Pitch 0.5mm, IPC Medium Density)
footprint PQFP208_L (Shrink QFP, 208-Leads, Body 28x28mm, Pitch 0.5mm, IPC High Density)
footprint PQFP208_M (Shrink QFP, 208-Leads, Body 28x28mm, Pitch 0.5mm, IPC Low Density)
3D model EPM3512A-PQFP208 (208-Pin Plastic Quad Flat Pack (PQFP208))
signal-integrity model max3ka (MAX 3000A)
part A pins: 169 IO (io), 170 IO (io), 171 IO (io), 172 IO (io), 173 IO (io), 175 IO (io), 177 IO (io), 178 IO (io)
part B pins: 159 IO (io), 160 IO (io), 161 IO (io), 162 IO (io), 163 IO (io), 164 IO (io), 166 IO (io), 167 IO (io), 168 IO (io)
part C pins: 147 IO (io), 148 IO (io), 149 IO (io), 150 IO (io), 151 IO (io), 153 IO (io), 154 IO (io), 155 IO (io), 156 IO (io), 157 IO (io)
part D pins: 135 IO (io), 136 IO (io), 137 IO (io), 138 IO (io), 139 IO (io), 140 IO (io), 141 IO (io), 142 IO (io), 144 IO (io), 145 IO (io), 146 IO (io)
part E pins: 122 IO (io), 123 IO (io), 124 IO (io), 126 IO (io), 128 IO (io), 129 IO (io), 130 IO (io), 131 IO (io), 132 IO (io), 133 IO (io)
part F pins: 109 IO (io), 110 IO (io), 111 IO (io), 112 IO (io), 113 IO (io), 114 IO (io), 115 IO (io), 117 IO (io), 118 IO (io), 119 IO (io), 120 IO (io), 121 IO (io)
part G pins: 95 IO (io), 96 IO (io), 97 IO (io), 98 IO (io), 99 IO (io), 100 IO (io), 101 IO (io), 102 IO (io), 103 IO (io), 104 IO (io), 106 IO (io)
part H pins: 79 IO (io), 80 IO (io), 81 IO (io), 86 IO (io), 87 IO (io), 88 IO (io), 89 IO (io), 90 IO (io), 91 IO (io), 92 IO (io), 93 IO (io)
part I pins: 64 IO (io), 65 IO (io), 66 IO (io), 67 IO (io), 68 IO (io), 69 IO (io), 70 IO (io), 71 IO (io), 73 IO (io), 76 IO (io), 77 IO (io), 78 IO (io)
part J pins: 49 IO (io), 52 IO (io), 53 IO (io), 54 IO (io), 55 IO (io), 56 IO (io), 57 IO (io), 58 IO (io), 59 IO (io), 60 IO (io), 61 IO (io), 62 IO (io)
part K pins: 36 IO (io), 37 IO (io), 38 IO (io), 39 IO (io), 42 IO (io), 43 IO (io), 44 IO (io), 45 IO (io), 46 IO (io), 47 IO (io), 48 IO (io)
part L pins: 24 IO (io), 25 IO (io), 26 IO (io), 27 IO (io), 28 IO (io), 29 IO (io), 31 IO (io), 33 IO (io), 34 IO (io), 35 IO (io)
part M pins: 11 IO (io), 12 IO (io), 13 IO (io), 15 IO (io), 16 IO (io), 17 IO (io), 18 IO (io), 19 IO (io), 20 IO (io), 21 IO (io), 22 IO (io)
part N pins: 1 IO (io), 2 IO (io), 3 IO (io), 4 IO (io), 7 IO (io), 8 IO (io), 9 IO (io), 10 IO (io), 208 IO (io)
part O pins: 197 IO (io), 198 IO (io), 199 IO (io), 201 IO (io), 202 IO (io), 203 IO (io), 204 IO (io), 205 IO (io), 206 IO (io)
part P pins: 187 IO (io), 188 IO (io), 190 IO (io), 192 IO (io), 193 IO (io), 194 IO (io), 195 IO (io), 196 IO (io)
part Q pins: 181 INPUT/OE2/GCLK2 (in), 182 INPUT/GCLRn (in), 183 INPUT/OE1 (in), 184 INPUT/GCLK1 (in)
part R pins: 30 IO/TCK (io), 127 IO/TMS (io), 176 IO/TDI (io), 189 IO/TDO (io)
part S pins: 5 VCCIO (power), 23 VCCIO (power), 41 VCCIO (power), 63 VCCIO (power), 74 VCCINT (power), 83 VCCINT (power), 85 VCCIO (power), 105 VCCIO (power), 107 VCCIO (power), 125 VCCIO (power), 143 VCCIO (power), 165 VCCIO (power), 179 VCCINT (power), 186 VCCINT (power), 191 VCCIO (power), 207 VCCIO (power)
part T pins: 6 GNDIO (power), 14 GNDIO (power), 32 GNDIO (power), 40 GNDIO (power), 50 GNDIO (power), 51 GNDIO (power), 72 GNDIO (power), 75 GNDINT (power), 82 GNDINT (power), 84 GNDIO (power), 94 GNDIO (power), 108 GNDIO (power), 116 GNDIO (power), 134 GNDIO (power), 152 GNDIO (power), 158 GNDIO (power), 174 GNDIO (power), 180 GNDINT (power), 185 GNDINT (power), 200 GNDIO (power)

## FH-103N
designator X?  (value not drawn)
footprint FH-103N
pins: 1, 2

## GH 20-4-7
designator HL?
footprint GH 20-4-7
pins: 1 COM1, 2 F1 H1 E1, 3 A1 D1 G1 , 4 K1 B1 C1  , 5 F2  H2 E2, 6 A2 D2 G2  , 7 K2 B2 C2  , 8 F3  H3 E3, 9 A3 D3 G3, 10 K3 C3 B3 , 11 F4 H4 E4, 12 A4 D4 G4 , 13 K4 B4 C4, 14 COM2, 15 COM3

## HCPL-0630
designator VU?
footprint SO8-HCPL (SOIC, 8-Leads, Body 4.9x3.9mm, Pitch 1.27mm, IPC Low Density)
part A pins: 1 ANOD, 2 CAT, 5 GND, 7 ~{VOUT}, 8 VCC
part B pins: 3 CAT, 4 ANOD, 5 GND, 6 ~{VOUT}, 8 VCC

## HMC1010LP4E
designator DA?  (value not drawn)
footprint HMC1010LP4E - duplicate
pins: 1 Vcc, 2 GND, 3 IN+, 4 IN-, 5 GND, 6 GND, 7 ENX, 8 GND, 9 COFSA, 10 COFSB, 11 GND, 12 GND, 13 GND, 14 VSET, 15 RMSOUT, 16 Vcc, 17 SCI1, 18 SCI2, 19 SCI3, 20 SCI4, 21 Vcc, 22 GND, 23 Vcc, 24 GND, 25 GND

## HS1K
designator VD?  (value not drawn)
Silicon Switching Diode Array for High-Speed Switching
footprint SMA
pins: 1 A, 2 C

## ID-4DP44-MF
designator HL?
footprint ID-4DP44-MF
pins: 1 COM1, 2 COM2, 3 COM3, 4 F1  E1, 5 A1  G1  D1, 6 B1  C1  -, 7 F2  E2  -, 8 A2  G2  D2, 9 B2  C2  H2, 10 F3  E3  -, 11 A3  G3  D3, 12 B3  C3  -, 13 F4  E4  I4, 14 A4  G4  D4, 15 B4  C4  H4, 16 A5  -  C5

## IDC-16
designator X?, comment IDC16  (value not drawn)
footprint IDC16
pins: 1, 2, 3, 4, 5, 6, 7, 8, 9, 10, 11, 12, 13, 14, 15, 16

## IRLL2703
designator VT?
HEXFET Power MOSFET; Note: Pin 2 is electrically connected to pin 4.
footprint SOT223 (SOT-223/SC-73; 4 Leads; Body 6.7 x 7.3 mm, inc. leads (LxW max))
pins: 1 G, 2 D, 3 S, 4 D

## IRLL2705
designator VT?
HEXFET Power MOSFET; Note: Pin 2 is electrically connected to pin 4.
footprint SOT223 (SOT-223/SC-73; 4 Leads; Body 6.7 x 7.3 mm, inc. leads (LxW max))
pins: 1 G, 2 D, 3 S, 4 D

## IRLML2803
designator VT?
HEXFET Power MOSFET
footprint SOT23-3L (SOT23, 3-Leads, Body 2.9x1.3mm, Pitch 0.95mm, Lead Span 2.5mm, IPC High Density)
pins: 1 G, 2 S, 3 D

## IRLML5803
designator VT?
HEXFET Power MOSFET
footprint SOT23-3L (SOT23, 3-Leads, Body 2.9x1.3mm, Pitch 0.95mm, Lead Span 2.5mm, IPC High Density)
pins: 1 G, 2 S, 3 D

## IT-1187U
designator SB?, comment IT-1187U-160G-G
footprint IT-1187 (SOIC, 4-Leads, Body 5,20x5,20mm, Pitch 1,27mm, IPC Medium Density)
pins: 1, 2, 3, 4

## Jumper
designator P?, comment jmp  (value not drawn)
footprint Jump
pins: 1 N2, 2 N1

## Jumper3
designator X?, comment pls  (value not drawn)
footprint JUMP3
pins: 1 N1, 2 N2, 3 N3

## K50-35-8
designator C?, comment 10 мкФ
конденсатор
footprint K50-35-8
pins: 1, 2

## K50-98-63V-1500uF
designator C?, comment 1500uF
footprint K50-98-63V-1500uF
pins: 1, 2

## K50-104-63V-2200uF
designator C?, comment 2200uF
footprint K50-104-63V-2200uF
pins: 1, 2

## K73-17
designator C?, comment 0,1 мкФ
планарный конденсатор
footprint K73-17
pins: 1, 2

## Klemma1
designator XS?  (value not drawn)
PLS-1
footprint KlemmaD1
pins: 1

## KlemmaD1
designator XS?  (value not drawn)
footprint KlemmaD1
pins: 1

## KLEMMNIK2
designator X?  (value not drawn)
footprint KLEMNIK2
pins: 1, 2

## KLEMMNIK3
designator X?  (value not drawn)
footprint KLEMNIK3 -SMD
pins: 1, 2, 3

## KMZ60
designator DA?
footprint SOIC127P600-8BM (SOIC, 8-Leads, Body 4.9x3.9mm, Pitch 1.27mm, IPC Low Density)
pins: 1 TCCEN, 2 VOUT1, 3 GND, 4 VOUT2, 5 VTEMP, 6 GND, 7 VCC, 8 PDEN

## KTC31003A1
designator VT?
footprint N-8_A (DIP; 8 Leads; Row Spacing 7.62 mm; Pitch 2.54 mm)
part A pins: 2 COLLEC (oe), 3 BASE (oc), 4 EMIT (in)
part B pins: 5 EMIT (in), 6 BASE (oc), 7 COLLEC (oe)

## L0805
designator L?, comment 151 нГн
footprint INDC2012L (Chip Inductor, Body 2.0x1.2mm, IPC High Density)
pins: 1, 2

## LJE0372
designator XS?
footprint JACK-MONO
pins: 1 R, 2 RS, 3 TS, 4 T, 5 S

## LM358
designator DA?
OP AMP
footprint SOIC127P600X175-8N
part A pins: 4 VCC- (power), 8 VCC+ (power)
part B pins: 5 IN+ (in), 6 IN- (in), 7 OUT (out)
part C pins: 1 OUT (out), 2 IN- (in), 3 IN+ (in)

## LM555
designator DA?
TIMER
footprint SOIC127P600-8BM (SOIC, 8-Leads, Body 4.9x3.9mm, Pitch 1.27mm, IPC Low Density)
pins: 1 GND, 2 TRG (in), 3 OUT, 4 RES (out), 5 CV (power), 6 TRS (in), 7 DSC (in), 8 VCC

## LM1117
designator DA?
footprint SOT223 (SOT-223/SC-73; 4 Leads; Body 6.7 x 7.3 mm, inc. leads (LxW max))
pins: 1 GND, 2 VOUT, 3 VIN, 4 VOUT

## LM1117-ADJ
designator DA?
footprint SOT223 (SOT-223/SC-73; 4 Leads; Body 6.7 x 7.3 mm, inc. leads (LxW max))
pins: 1 ADJ, 2 VOUT, 3 VIN, 4 VOUT

## LM3488
designator *
footprint UMAX8 (Shrink Small Outline; 8 Leads; Body Width 3 mm; Pitch 0.65 mm)
pins: 1 ISEN, 2 COMP, 3 FB, 4 AGND (power), 5 PGND (power), 6 DR, 7 SD, 8 VIN (power)

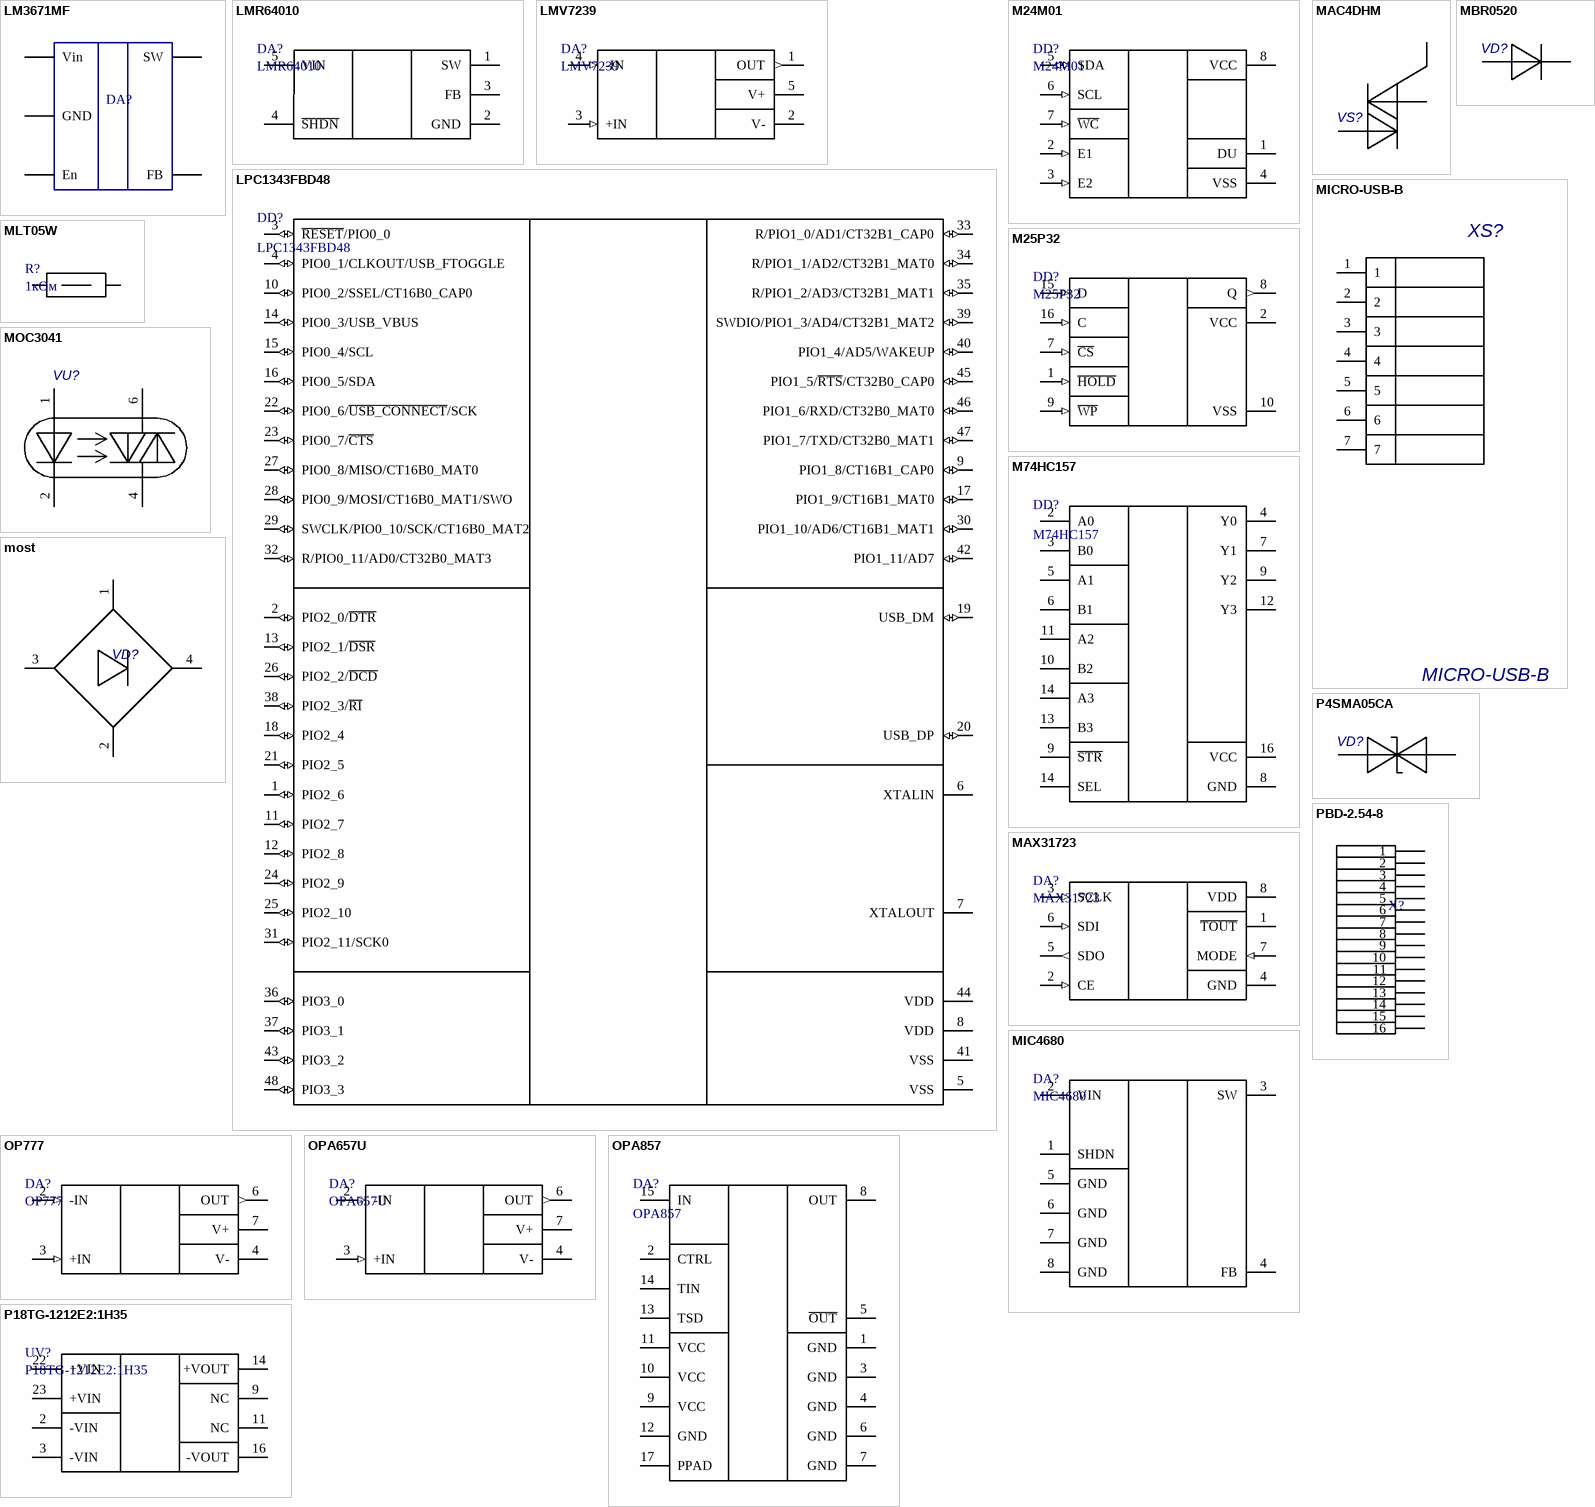
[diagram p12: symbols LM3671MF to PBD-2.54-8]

## LM3671MF
designator DA?  (value not drawn)
footprint SOT23-5AM (SOT23, 5-Leads, Body 2.9x1.7mm, Pitch 0.95mm, Lead Span 2.8mm, IPC Low Density)
pins: 1 Vin, 2 GND, 3 En, 4 FB, 5 SW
